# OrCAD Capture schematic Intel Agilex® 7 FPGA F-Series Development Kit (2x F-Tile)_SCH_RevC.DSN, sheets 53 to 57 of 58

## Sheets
53 PG57 VCCIO_SDM, VCCFUSEWR_SDM: size C
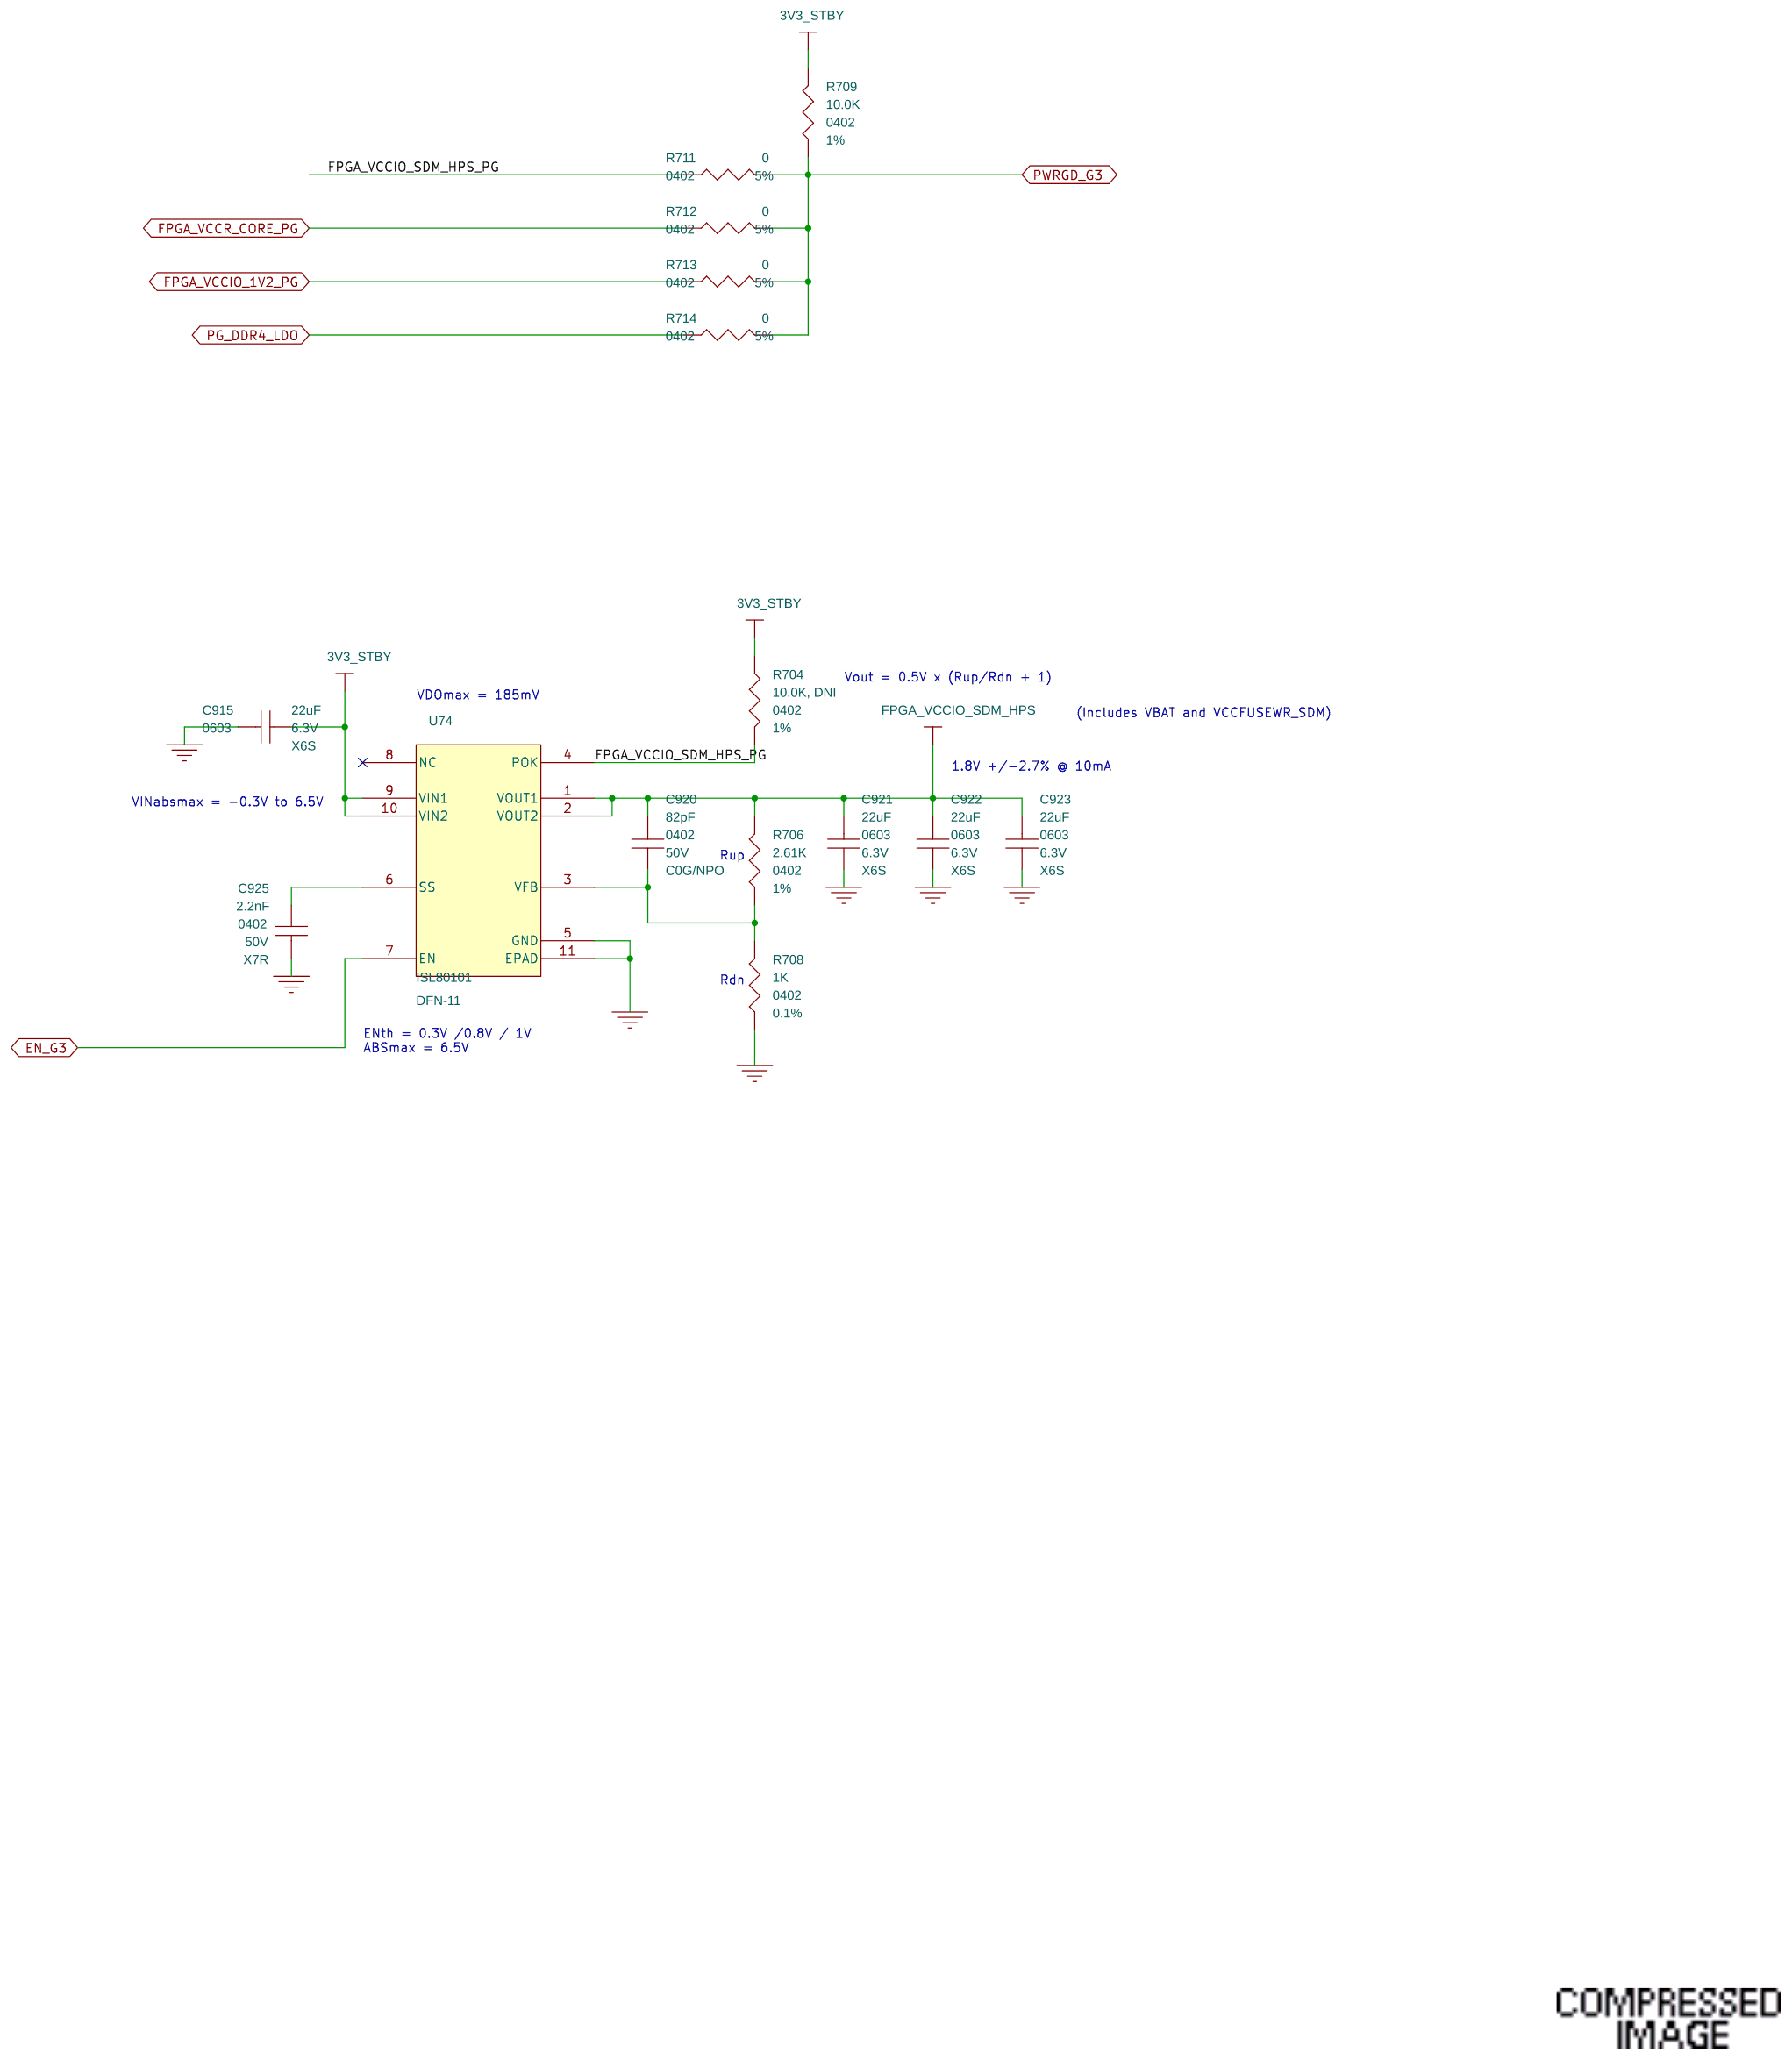
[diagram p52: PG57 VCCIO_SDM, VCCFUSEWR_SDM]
54 PG58 2V5_DDR4, DDR4 VTT, VREF: size C
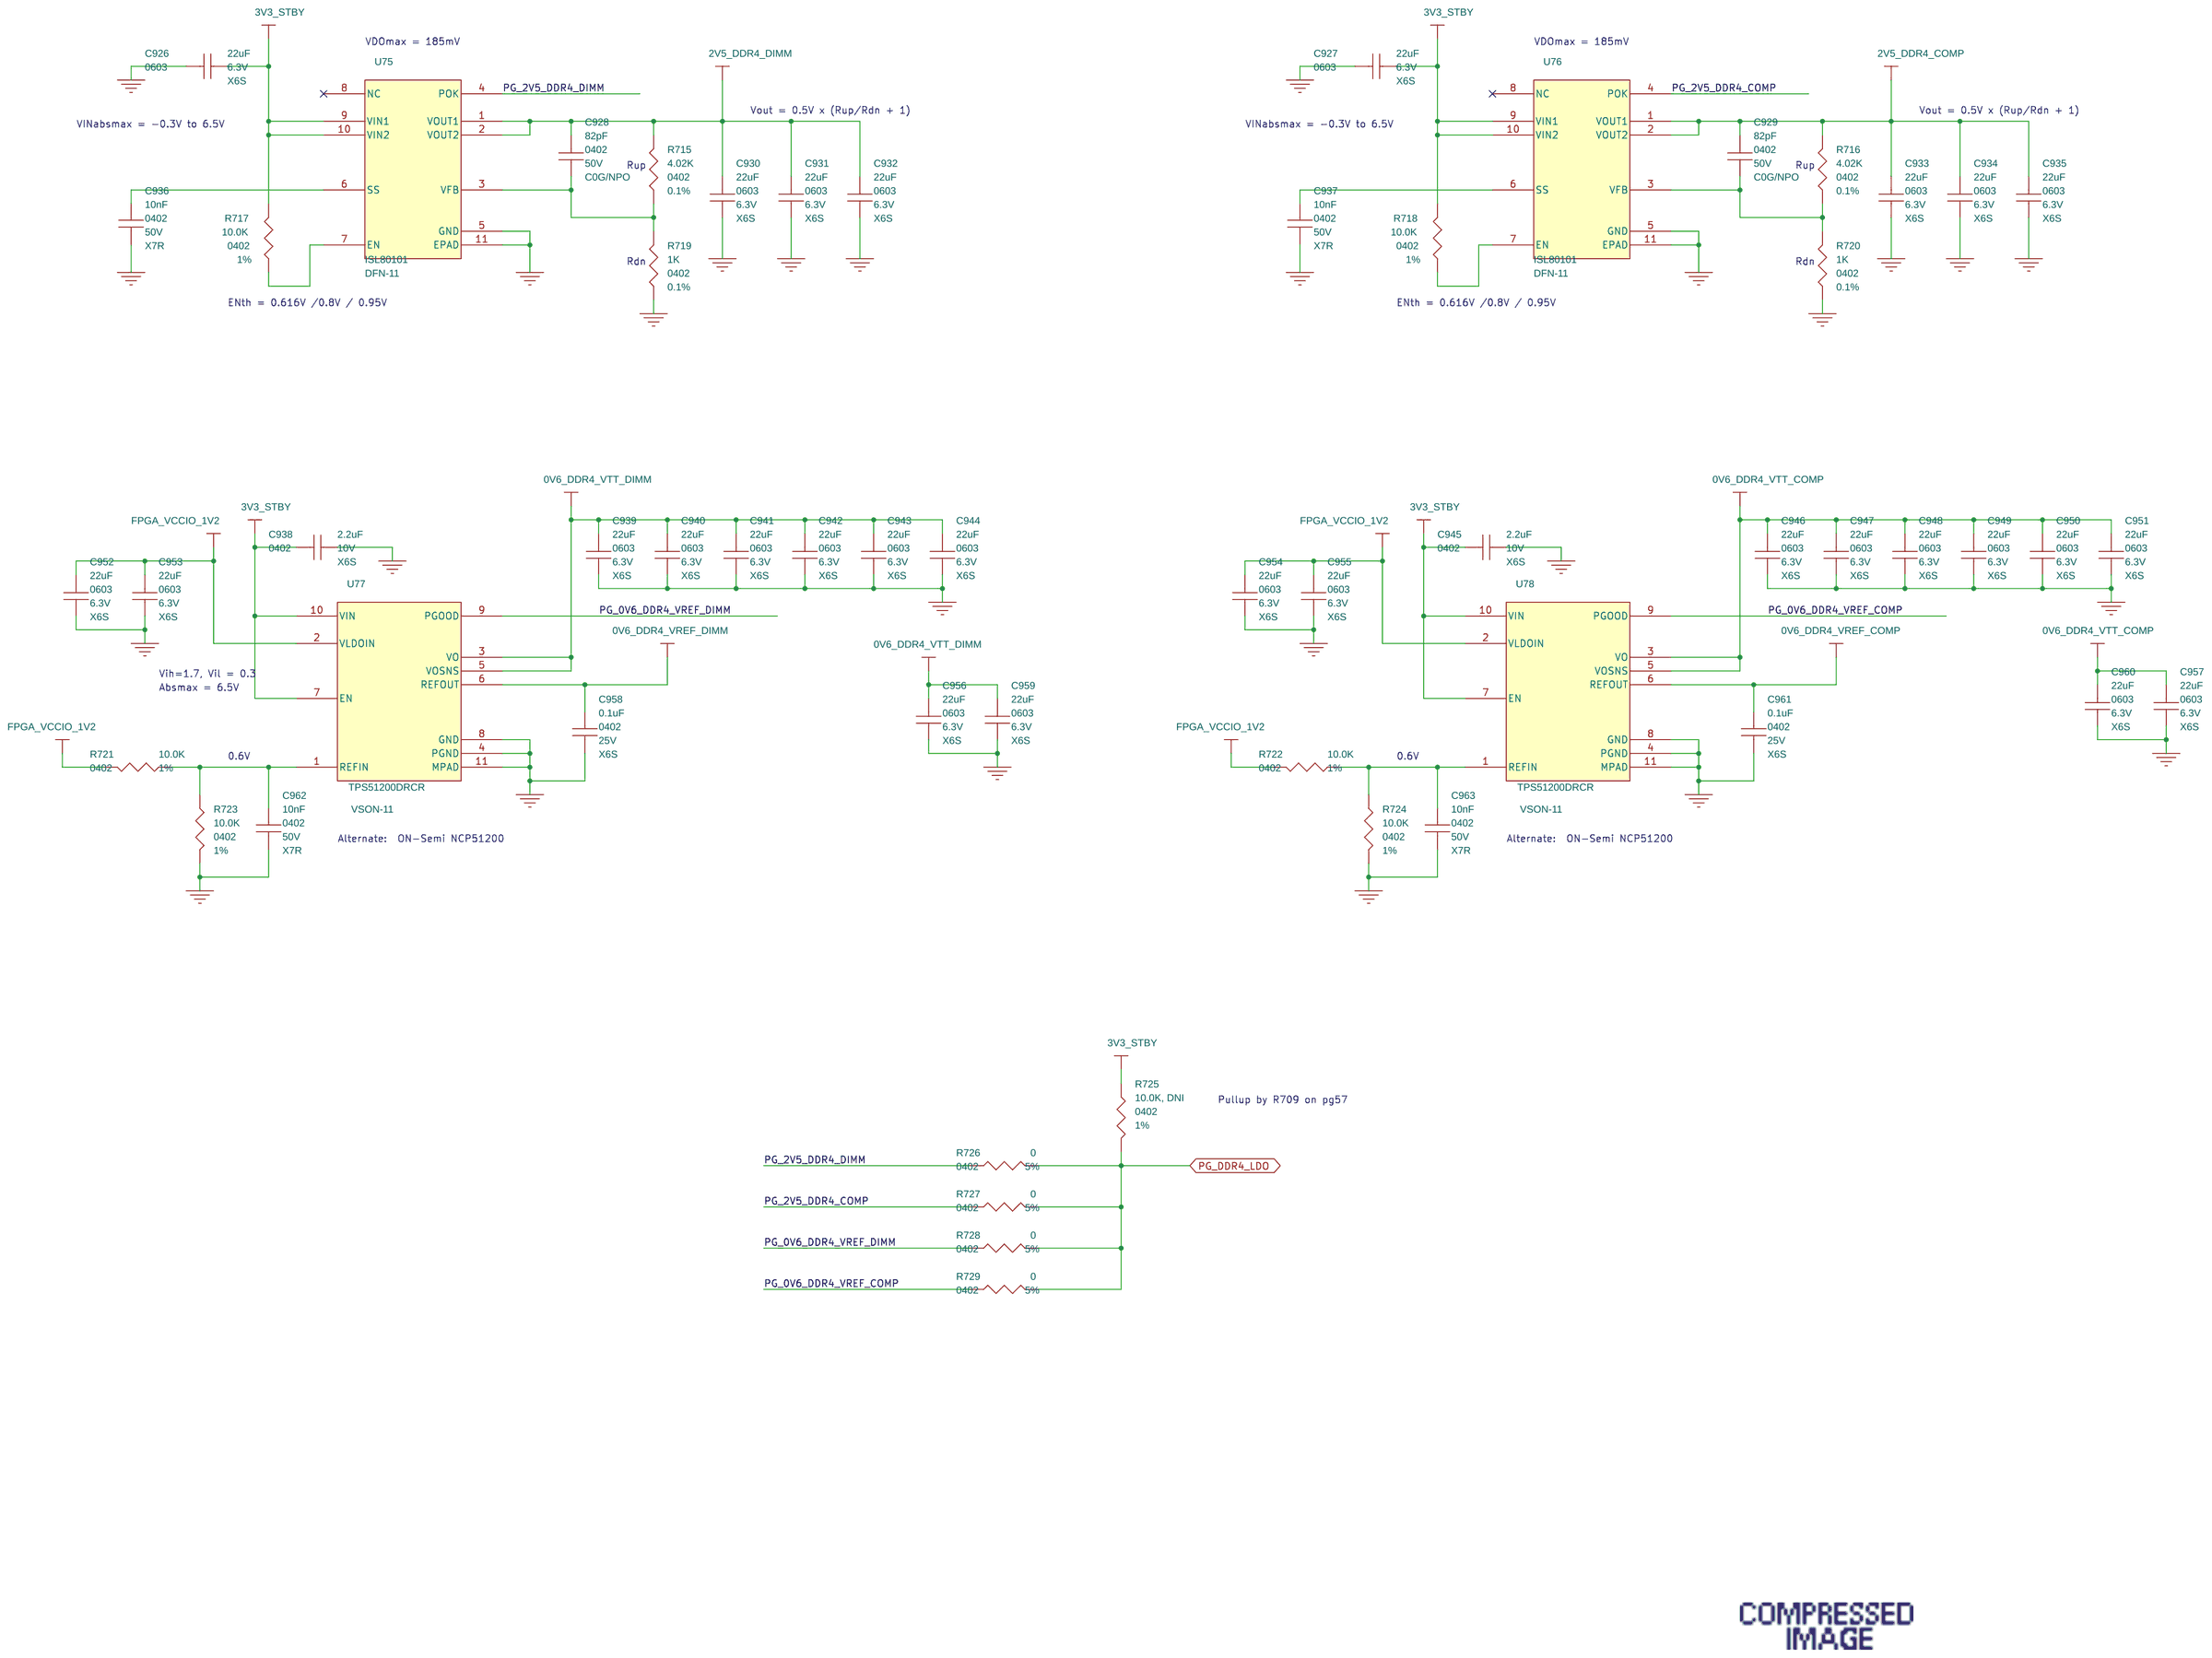
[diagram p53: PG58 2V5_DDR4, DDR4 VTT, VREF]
55 PG26 DDR4/DDR-T DIMM1: size C
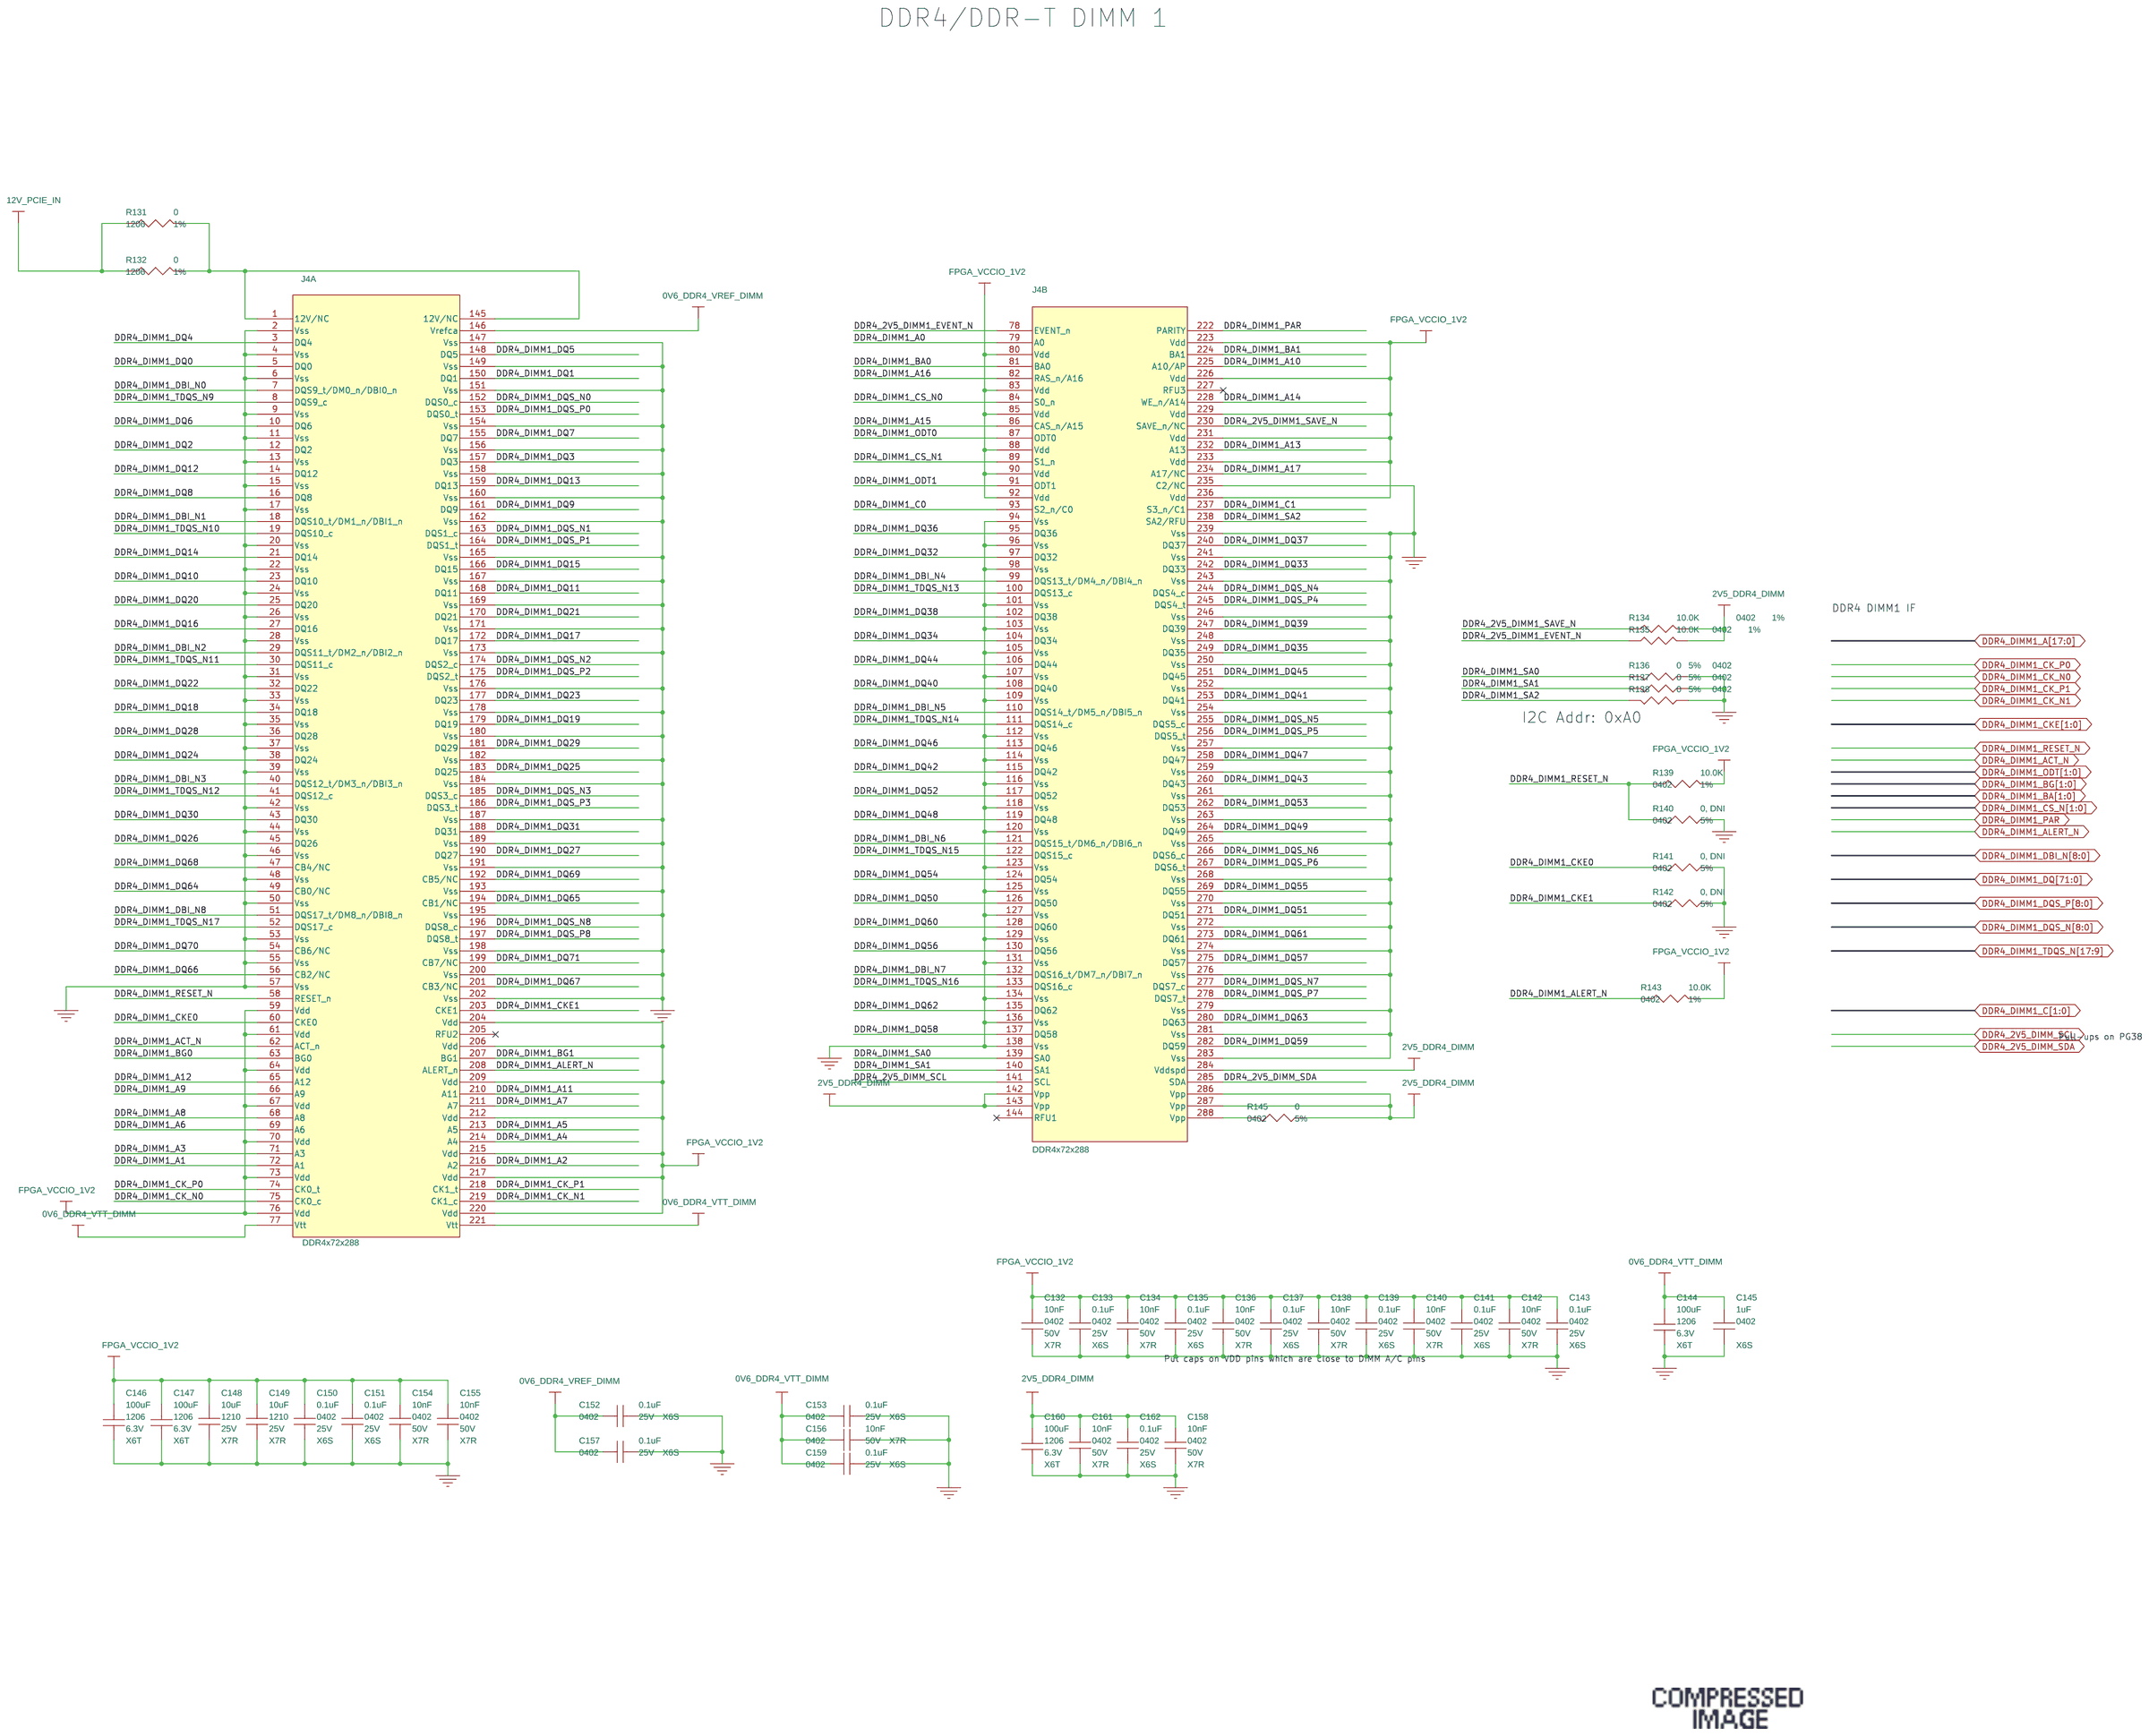
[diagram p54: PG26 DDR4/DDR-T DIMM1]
56 PG27 DDR4/DDR-T DIMM2: size C
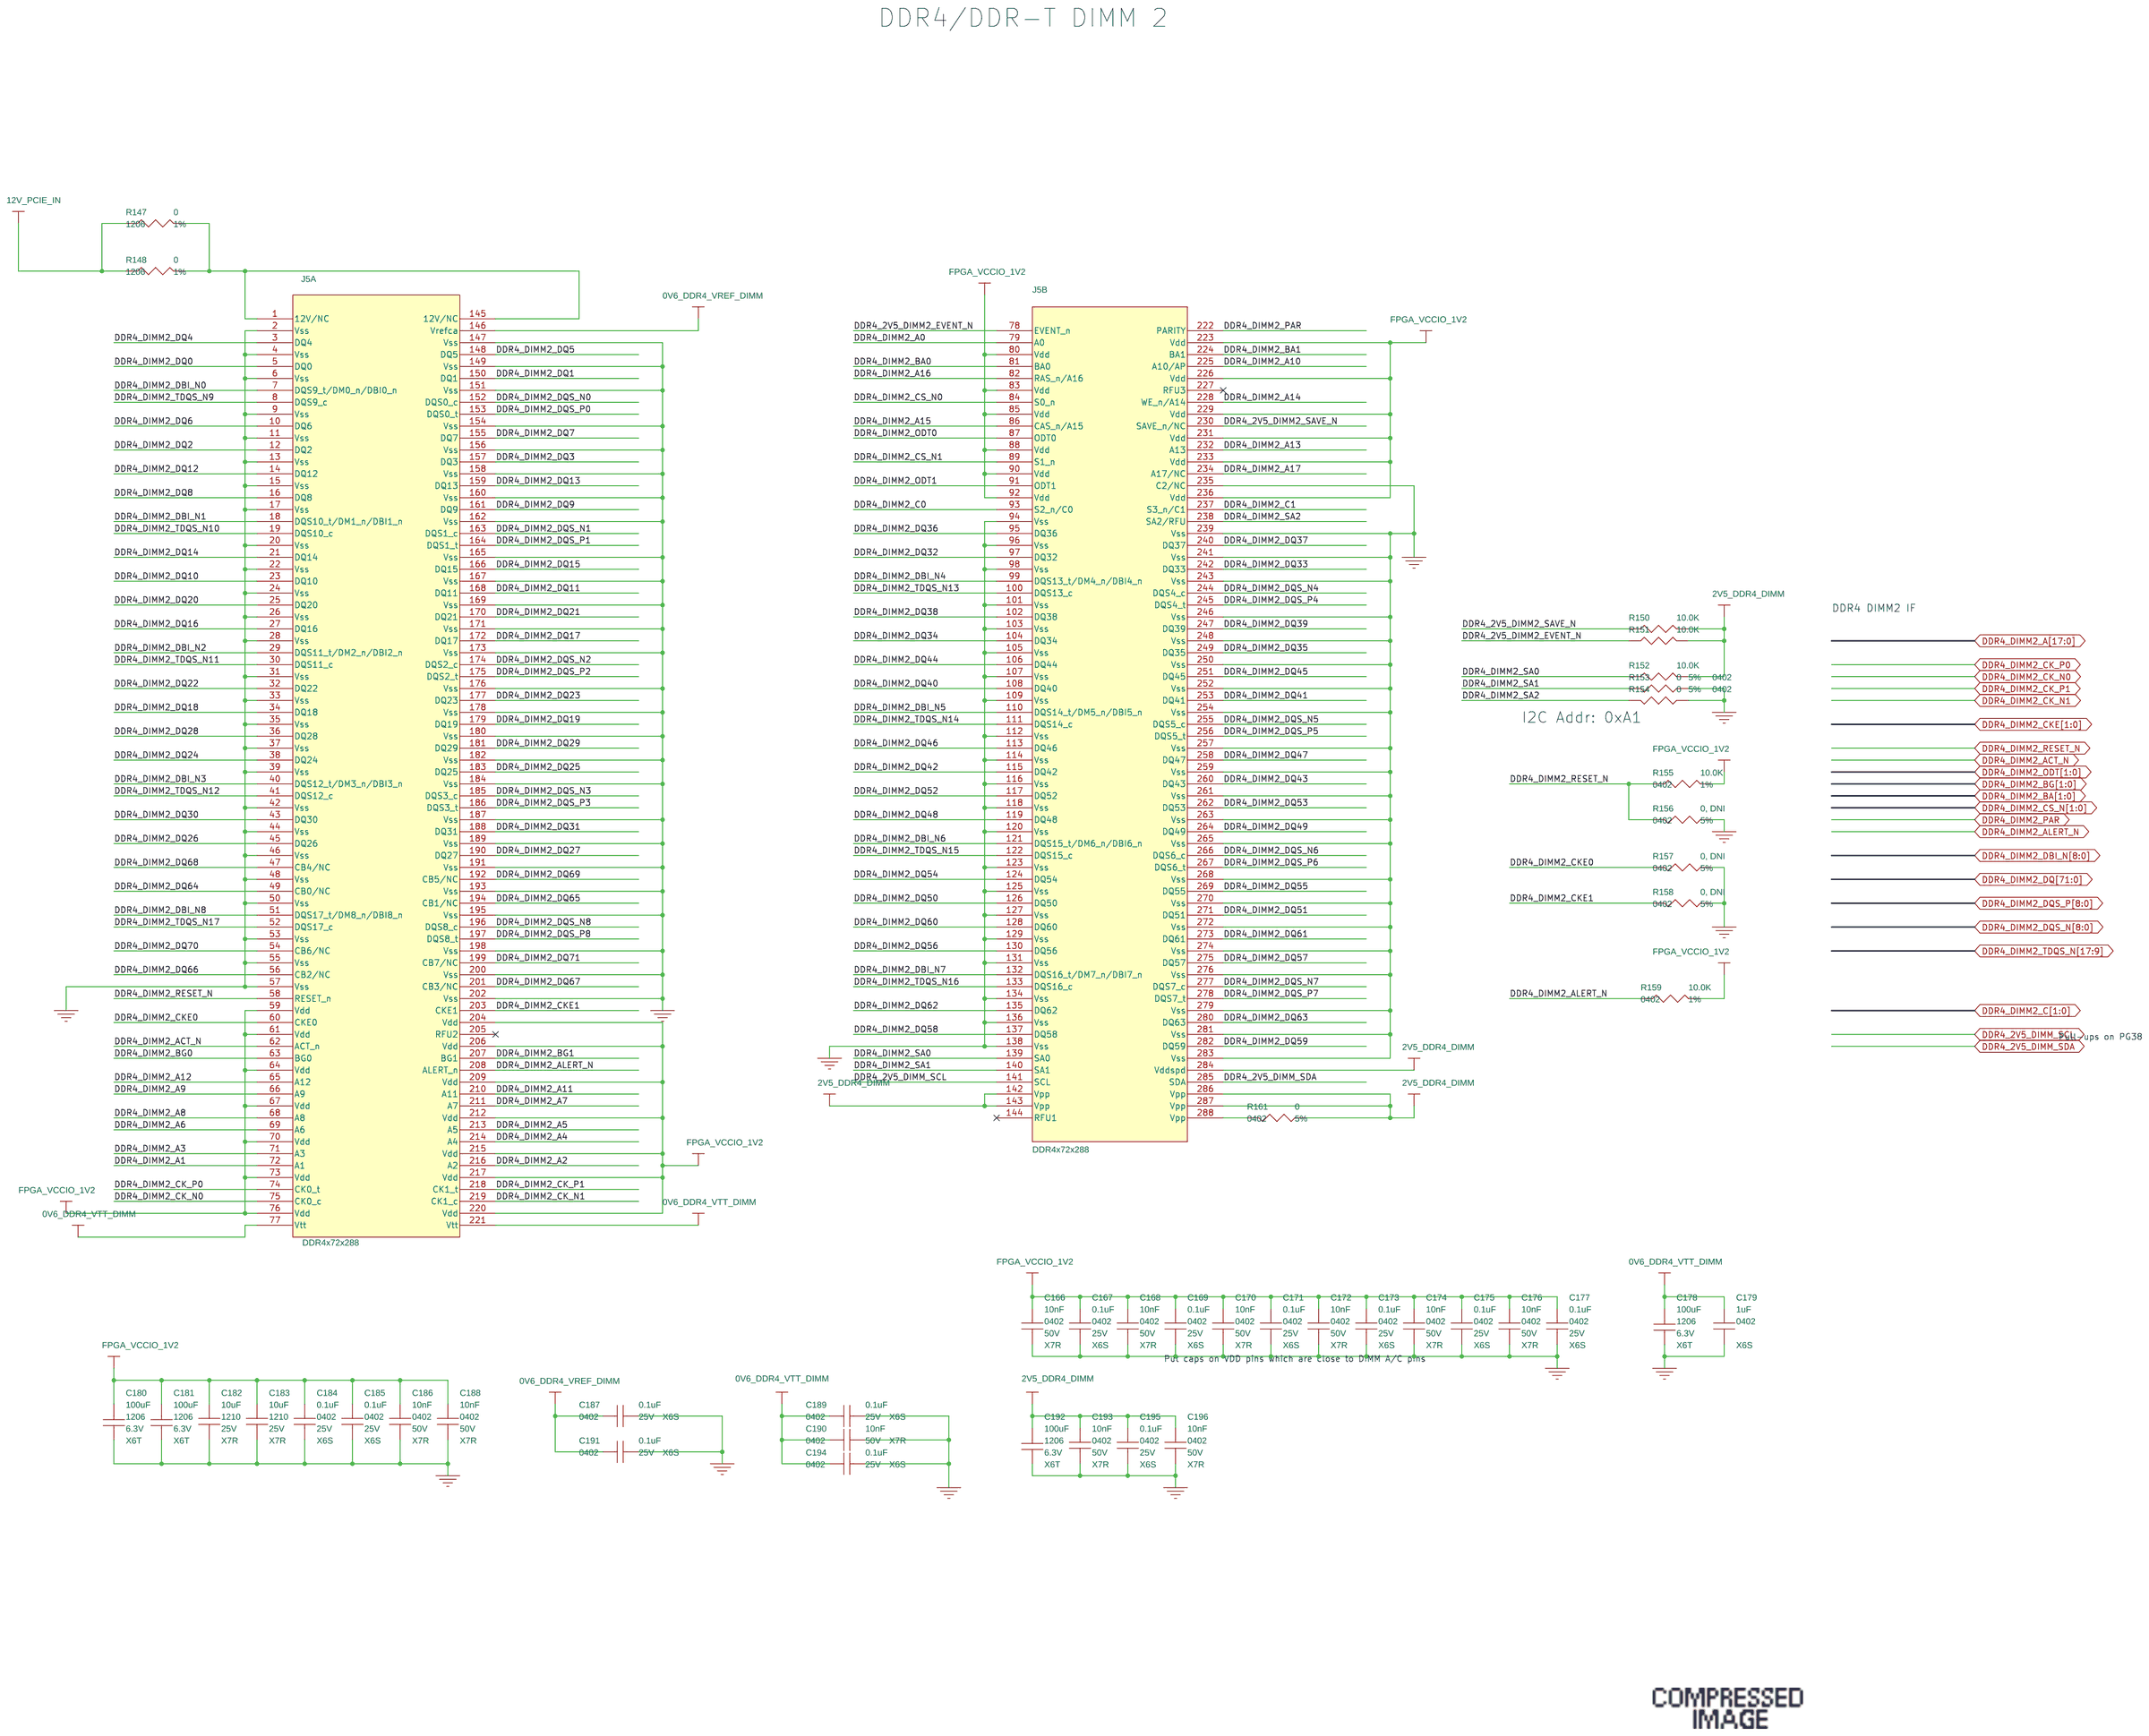
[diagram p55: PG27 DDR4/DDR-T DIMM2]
57 PG25 DDR4/DDR-T PIN MAP
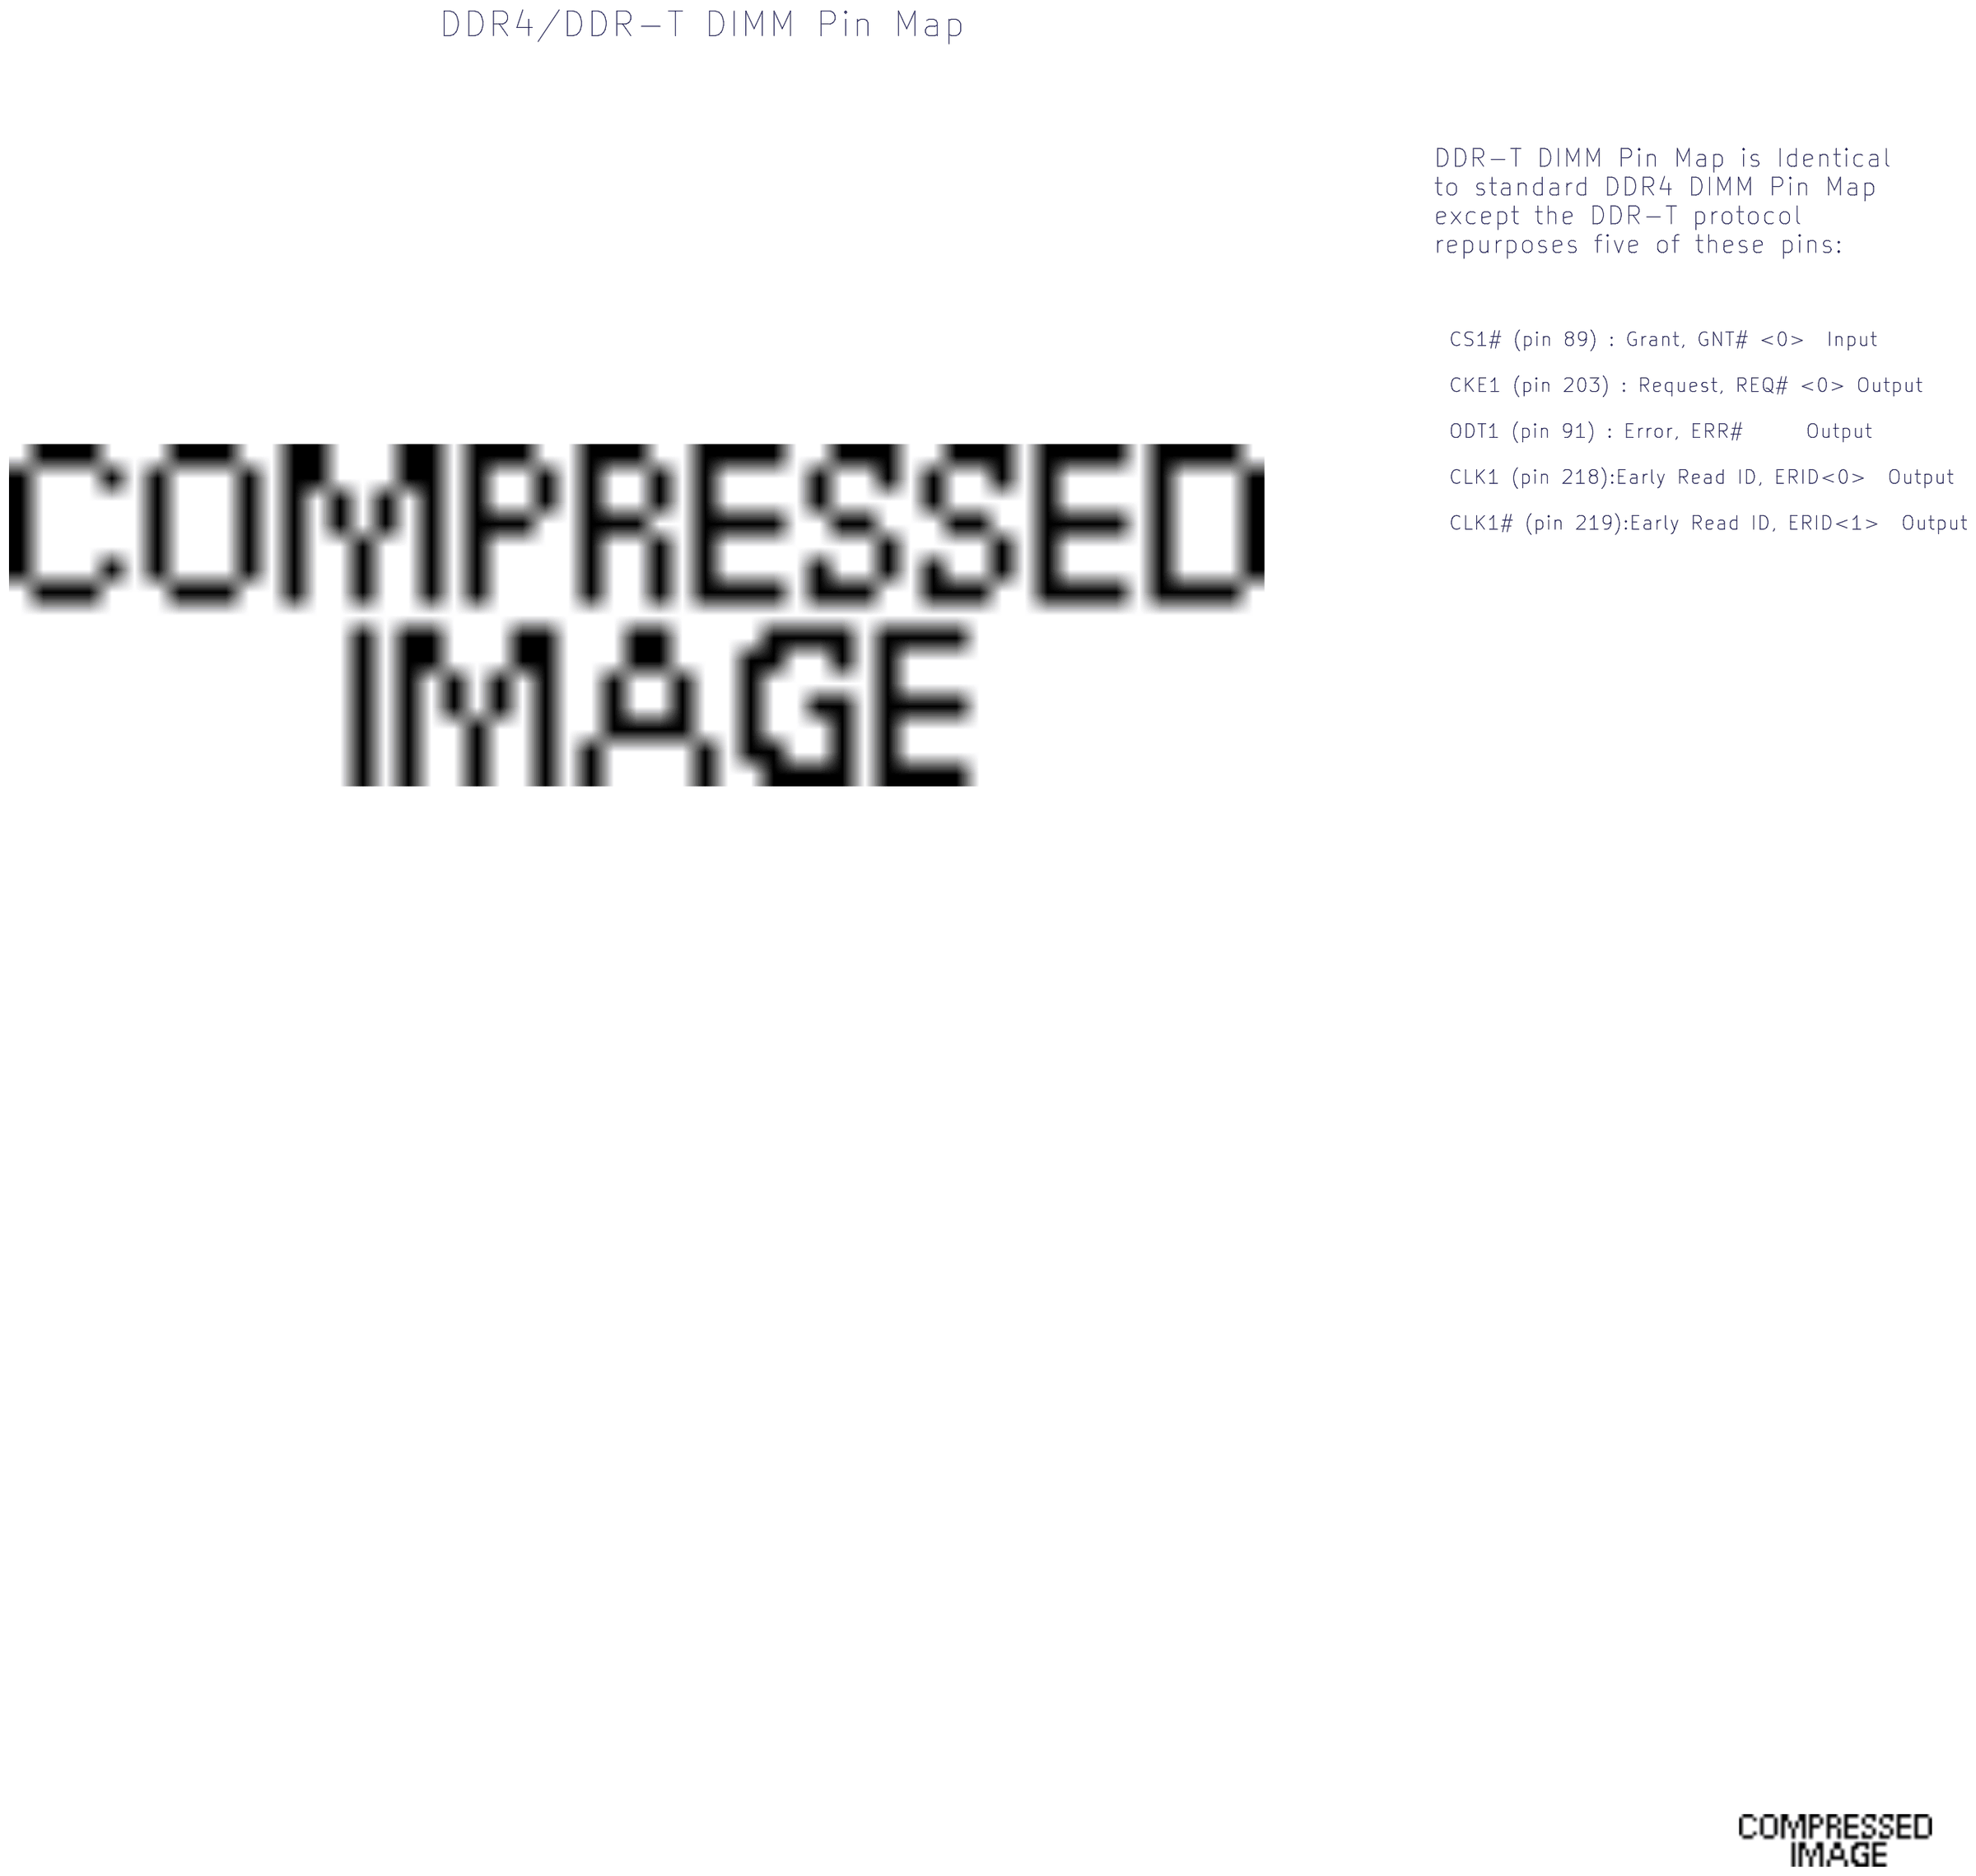
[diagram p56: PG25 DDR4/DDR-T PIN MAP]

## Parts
sheet PG26 DDR4/DDR-T DIMM1
C132  10nF  [0402]
C133  0.1uF  [0402]
C134  10nF  [0402]
C135  0.1uF  [0402]
C136  10nF  [0402]
C137  0.1uF  [0402]
C138  10nF  [0402]
C139  0.1uF  [0402]
C140  10nF  [0402]
C141  0.1uF  [0402]
C142  10nF  [0402]
C143  0.1uF  [0402]
C144  100uF  [1206]
C145  1uF  [0402]
C146  100uF  [1206]
C147  100uF  [1206]
C148  10uF  [1210_H2p2mm]
C149  10uF  [1210_H2p2mm]
C150  0.1uF  [0402]
C151  0.1uF  [0402]
C152  0.1uF  [0402]
C153  0.1uF  [0402]
C154  10nF  [0402]
C155  10nF  [0402]
C156  10nF  [0402]
C157  0.1uF  [0402]
C158  10nF  [0402]
C159  0.1uF  [0402]
C160  100uF  [1206]
C161  10nF  [0402]
C162  0.1uF  [0402]
J4  DDR4x72x288  [DDR4DIMM_SMT]  (sections A,B)
R131  0  [1206]
R132  0  [1206]
R134  10.0K  [0402]
R135  10.0K  [0402]
R136  0  [0402]
R137  0  [0402]
R138  0  [0402]
R139  10.0K  [0402]
R140  0, DNI  [0402]
R141  0, DNI  [0402]
R142  0, DNI  [0402]
R143  10.0K  [0402]
R145  0  [0402]
sheet PG27 DDR4/DDR-T DIMM2
C166  10nF  [0402]
C167  0.1uF  [0402]
C168  10nF  [0402]
C169  0.1uF  [0402]
C170  10nF  [0402]
C171  0.1uF  [0402]
C172  10nF  [0402]
C173  0.1uF  [0402]
C174  10nF  [0402]
C175  0.1uF  [0402]
C176  10nF  [0402]
C177  0.1uF  [0402]
C178  100uF  [1206]
C179  1uF  [0402]
C180  100uF  [1206]
C181  100uF  [1206]
C182  10uF  [1210_H2p2mm]
C183  10uF  [1210_H2p2mm]
C184  0.1uF  [0402]
C185  0.1uF  [0402]
C186  10nF  [0402]
C187  0.1uF  [0402]
C188  10nF  [0402]
C189  0.1uF  [0402]
C190  10nF  [0402]
C191  0.1uF  [0402]
C192  100uF  [1206]
C193  10nF  [0402]
C194  0.1uF  [0402]
C195  0.1uF  [0402]
C196  10nF  [0402]
J5  DDR4x72x288  [DDR4DIMM_SMT]  (sections A,B)
R147  0  [1206]
R148  0  [1206]
R150  10.0K  [0402]
R151  10.0K  [0402]
R152  10.0K  [0402]
R153  0  [0402]
R154  0  [0402]
R155  10.0K  [0402]
R156  0, DNI  [0402]
R157  0, DNI  [0402]
R158  0, DNI  [0402]
R159  10.0K  [0402]
R161  0  [0402]
sheet PG57 VCCIO_SDM, VCCFUSEWR_SDM
C915  22uF  [0603]
C920  82pF  [0402]
C921  22uF  [0603]
C922  22uF  [0603]
C923  22uF  [0603]
C925  2.2nF  [0402]
R704  10.0K, DNI  [0402]
R706  2.61K  [0402]
R708  1K  [0402]
R709  10.0K  [0402]
R711  0  [0402]
R712  0  [0402]
R713  0  [0402]
R714  0  [0402]
U74  ISL80101  [DFN-11]
sheet PG58 2V5_DDR4, DDR4 VTT, VREF
C926  22uF  [0603]
C927  22uF  [0603]
C928  82pF  [0402]
C929  82pF  [0402]
C930  22uF  [0603]
C931  22uF  [0603]
C932  22uF  [0603]
C933  22uF  [0603]
C934  22uF  [0603]
C935  22uF  [0603]
C936  10nF  [0402]
C937  10nF  [0402]
C938  2.2uF  [0402]
C939  22uF  [0603]
C940  22uF  [0603]
C941  22uF  [0603]
C942  22uF  [0603]
C943  22uF  [0603]
C944  22uF  [0603]
C945  2.2uF  [0402]
C946  22uF  [0603]
C947  22uF  [0603]
C948  22uF  [0603]
C949  22uF  [0603]
C950  22uF  [0603]
C951  22uF  [0603]
C952  22uF  [0603]
C953  22uF  [0603]
C954  22uF  [0603]
C955  22uF  [0603]
C956  22uF  [0603]
C957  22uF  [0603]
C958  0.1uF  [0402]
C959  22uF  [0603]
C960  22uF  [0603]
C961  0.1uF  [0402]
C962  10nF  [0402]
C963  10nF  [0402]
R715  4.02K  [0402]
R716  4.02K  [0402]
R717  10.0K  [0402]
R718  10.0K  [0402]
R719  1K  [0402]
R720  1K  [0402]
R721  10.0K  [0402]
R722  10.0K  [0402]
R723  10.0K  [0402]
R724  10.0K  [0402]
R725  10.0K, DNI  [0402]
R726  0  [0402]
R727  0  [0402]
R728  0  [0402]
R729  0  [0402]
U75  ISL80101  [DFN-11]
U76  ISL80101  [DFN-11]
U77  TPS51200DRCR  [VSON-11]
U78  TPS51200DRCR  [VSON-11]

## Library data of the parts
C132 C134 C136 C138 C140 C142 C154-C156 C158 C161 C166 C168 C170 C172 C174 C176 C186 C188 C190 C193 C196 = Cap_10000PF_50V_0402: CAP - CER, 10NF, 50V, +/-10%, X7R, 0402 SMD; Dielectric: X7R; Item Num: H61346-001; LIFECYCLE_PHASE: Active; Lead Free Status: Lead Free; Manufacturer Part Num: GRM155R71H103KA88D; Num Pins: 2; Part Class: CAPACITORS; RATED_VOLTAGE: 50V; RoHS Compliant: RoHS Compliant; Temperature Coefficient: X7R; Tolerance: 10%; Voltage: 50V
C133 C135 C137 C139 C141 C143 C150-C153 C157 C159 C162 C167 C169 C171 C173 C175 C177 C184 C185 C187 C189 C191 C194 C195 C958 C961 = CAP: CAP CER 0.1UF 25V X6S 0402; Dielectric: X6S; IPN: K19434-001; Item Num: K19434-001; LIFECYCLE_PHASE: Active; Lead Free Status: Lead Free; MFR_LIFECYCLE: Active; Manufacturer: Murata; Manufacturer Part Num: GRM155C81E104KA12D; Num Pins: 2; PART_SUBCLASS: CAPACITORS; Part Class: CAPACITORS; RATED_VOLTAGE: 25V; RoHS Compliant: RoHS Compliant; Temperature Coefficient: X6S; Tolerance: 10%
C144 C146 C147 C160 C178 C180 C181 = CAP: CAP CER 100UF 6.3V X6T 1206; CLASS: DISCRETE; Dielectric Type: X6T; Item Num: H65271-004; LIFECYCLE_PHASE: Active; Lead Free Status: Lead Free; MFR_LIFECYCLE: Active; Manufacturer: Murata; Manufacturer PN: GRM31CR60J107ME39L; Manufacturer Part Num: GRM31CD80J107ME39L; Num Pins: 2; PART_SUBCLASS: CAPACITORS; RATED_VOLTAGE: 6.3V; Rated Voltage: 6.3V; RoHS Compliant: RoHS Compliant; TOLERANCE: 20%; Temperature Coefficient: X6T; Working Voltage: 6.3V
C145 C179 = CAP: CAP CER 1UF 25V X6S 0402; Item Num: H81594-001; Lead Free Status: Yes; Manufacturer: Murata; Manufacturer Part Num: GRM155C81E105KE11D; Num Pins: 2; Part Class: CAPACITORS; RATED_VOLTAGE: 25V; RoHS Compliant: Yes; Temperature Coefficient: X6S
C148 C149 C182 C183 = CAP_10uF_+_-10%_25V_1210: CAP - CER, 10UF, 25V, 10%, X7R, 1210; Agile Part Description: CAP - CER, 10UF, 25V, 10%, X7R, 1210; Item Num: G10603-003; Manufacturer Part Num: GRM32DR71E106KA12L; Package: 1210; Temperature Coefficient: X7R; Voltage: 25V
J4 = DDR4x72x288_1: CONN SMT DDR4 288POS VERT; COMPGROUP: DDR4_DIMM1; Item Num: K21528-001; Manufacturer: Molex Inc; Manufacturer Part Num: 787301002
R131 R132 R147 R148 = RESISTOR: RES SMD 0 OHM JUMPER 3/4W 1206; AGILE_LINK: http://sj-agile9app/Agile/PLMServlet?action=OpenEmailObject&classid=10000&objid=146548997; Item Num: A93552-015; LIFECYCLE_PHASE: Active; Lead Free Status: No; MFR_LIFECYCLE: Active; Manufacturer: Vishay Dale; Manufacturer Part Num: CRCW12060000Z0EAHP; Num Pins: 2; PART_SUBCLASS: RESISTORS; POWER: 3/4W; RoHS Compliant: Yes; TOLERANCE: 1%
R134 R135 R139 R143 R150-R152 R155 R159 R709 R717 R718 R721-R724 = RESISTOR: RES,10.0K OHMS,1.0%,1/16W, 0402; AGILE_LINK: http://sj-agile9app/Agile/PLMServlet?action=OpenEmailObject&classid=10000&objid=146548997; Item Num: K28115-001; LIFECYCLE_PHASE: Active; Lead Free Status: Yes; MFR_LIFECYCLE: Active; Manufacturer: Panasonic; Manufacturer Part Num: ERJ-2RKF1002X; Num Pins: 2; PART_SUBCLASS: RESISTORS; POWER: 1/16W; RoHS Compliant: Yes; TOLERANCE: 1%
R136-R138 R145 R153 R154 R161 = RES_0_OHM_5%_1_16W_0402_SMD: Item Num: A93549-001; Manufacturer: Yageo; Manufacturer Part Num: RC0402JR-070RL; Num Pins: 2; RoHS Compliant: Yes; Tolerance: 5%
R140-R142 R156-R158 = RES_0_OHM_5%_1_16W_0402_SMD: IPN: A93549-001; Item Num: A93549-001; Lead Free Status: Yes; Manufacturer: Yageo; Manufacturer Part Num: RC0402JR-070RL; Num Pins: 2; Part Class: RESISTORS; RoHS Compliant: Yes; Tolerance: 5%
C192 = CAP: CAP CER 100UF 6.3V X6T 1206; Dielectric Type: X6T; Item Num: H65271-004; LIFECYCLE_PHASE: Active; Lead Free Status: Lead Free; MFR_LIFECYCLE: Active; Manufacturer: Murata; Manufacturer PN: GRM31CD80J107ME39L; Manufacturer Part Num: GRM31CD80J107ME39L; Num Pins: 2; PART_SUBCLASS: CAPACITORS; RATED_VOLTAGE: 6.3V; Rated Voltage: 6.3V; RoHS Compliant: RoHS Compliant; TOLERANCE: 20%; Temperature Coefficient: X6T; Working Voltage: 6.3V
J5 = DDR4x72x288_1: CONN SMT DDR4 288POS VERT; COMPGROUP: DDR4_DIMM2; Item Num: K21528-001; Manufacturer: Molex Inc; Manufacturer Part Num: 787301002
C915 C921-C923 C926 C927 C930-C935 C939-C944 C946-C957 C959 C960 = CAP: CAP CER 22UF 6.3V X6S 0603; AGILE_LINK: http://sj-agile9app/Agile/PLMServlet?action=OpenEmailObject&classid=10000&objid=257560276; Item Num: H63299-001; LIFECYCLE_PHASE: Active; Lead Free Status: Not Lead Free; MFR_LIFECYCLE: Active; Manufacturer: Murata; Manufacturer Part Num: GRM188C80J226ME15D; Num Pins: 2; PART_SUBCLASS: CAPACITORS; RATED_VOLTAGE: 6.3V; RoHS Compliant: RoHS Compliant; TOLERANCE: 20%; Temperature Coefficient: X6S
C920 C928 C929 = CAP: CAP CER 82PF 50V C0G/NPO 0402; Dielectric: C0G/NPO; Item Num: K13615-001; Lead Free Status: Yes; Manufacturer: Yageo; Manufacturer Part Num: CC0402JRNPO9BN820; Num Pins: 2; Part Class: CAPACITORS; RoHS Compliant: Yes; Temperature Coefficient: C0G/NPO; Tolerance: 5%; Voltage Rating: 50V
C925 = CAP: CAP CER 2200PF 50V 10% X7R 0402; CAPACITANCE: 2200pF; Dielectric: X7R; Item Num: K13631-001; LIFECYCLE_PHASE: Active; Lead Free Status: Lead Free; Manufacturer: TDK; Manufacturer Part Num: CGJ2B2X7R1E222K050BA; Num Pins: 2; PART_SUBCLASS: CAPACITORS; Part Class: CAPACITORS; RATED_VOLTAGE: 50V; RoHS Compliant: RoHS Compliant; Temperature Coefficient: X7R; Tolerance: +/-10%
R704 R725 = RESISTOR: RES,10.0K OHMS,1.0%,1/16W, 0402; AGILE_LINK: http://sj-agile9app/Agile/PLMServlet?action=OpenEmailObject&classid=10000&objid=146548997; Item Num: K28115-001; LIFECYCLE_PHASE: Active; Lead Free Status: Yes; MFR_LIFECYCLE: Active; Manufacturer: Panasonic; Manufacturer Part Num: ERJ-2RKF1002X; Num Pins: 2; PART_SUBCLASS: RESISTORS; POWER: 1/16W; RESISTANCE: 10.0K; RoHS Compliant: Yes; TOLERANCE: 1%
R706 = RESISTOR: RES SMD 2.61K 1% 1/16W 0402; Item Num: A93548-419; Lead Free Status: Yes; Manufacturer: RC0402FR-072K61L; Manufaturer: Yageo; Num Pins: 2; Part Class: RESISTORS; RoHS Compliant: Yes; TOLERANCE: 1%
R708 R719 R720 = RESISTOR: RES SMD 1K OHM 0.1% 1/16W 0402; Item Num: K21643-001; Lead Free Status: Yes; Manufacturer: Panasonic; Manufacturer Part Num: ERA-2AEB102X; Num Pins: 2; Part Class: Resistors; Power Rating: 1/16W; RoHS Compliant: Yes; TOLERANCE: 0.1%
R711-R714 R726-R729 = RESISTOR: RES ZERO OHM 1/16W 5% 0402 SMD; Item Num: A93549-001; Lead Free Status: Yes; Manufacturer: Yageo; Manufacturer Part Num: RC0402JR-070RL; Num Pins: 2; Part Class: RESISTORS; RoHS Compliant: Yes; Tolerance: 5%
U74-U76 = EY1501di-adj: IC, Linear Regulator, 1A; Item Num: E81353-001; Manufacturer: Intel/Enpirion; Manufacturer Part Num: EY1501DI-ADJ
C936 C937 C962 C963 = CAP: CAP - CER, 10NF, 50V, +/-10%, X7R, 0402 SMD; Dielectric: X7R; Item Num: H61346-001; LIFECYCLE_PHASE: Active; Lead Free Status: Lead Free; Manufacturer: Murata; Manufacturer Part Num: GRM155R71H103KA88D; Num Pins: 2; Part Class: CAPACITORS; RATED_VOLTAGE: 50V; RoHS Compliant: RoHS Compliant; Temperature Coefficient: X7R; Tolerance: 10%; Voltage: 50V
C938 C945 = CAP: CAP CER 2.2UF 10V X6S 0402; Dielectric: X6S; Item Num: H90637-001; LIFECYCLE_PHASE: Active; Lead Free Status: Lead Free; Manufacturer: Murata; Manufacturer Part Num: GRM155C81A225KE44D; Num Pins: 2; Part Class: CAPACITORS; RATED_VOLTAGE: 10V; RoHS Compliant: RoHS Compliant; Tolerance: 10%
R715 R716 = RESISTOR: RES SMD 4.02KOHM 0.1% 1/16W 0402; Item Num: K21642-001; Lead Free Status: Yes; Manufacturer: Panasonic; Manufacturer Part Num: ERA-2AEB4021X; Num Pins: 2; Part Class: RESISTORS; RoHS Compliant: Yes; TOLERANCE: 0.1%
U77 U78 = TPS51200_1: IC, Sink and Source DDR Termination Regulator; Item Num: H28999-001; Manufacturer: Texas Instruments

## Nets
0V6_DDR4_VREF_COMP: C961.1 U78.6(REFOUT) ; also on sheet 25 26 27
0V6_DDR4_VREF_DIMM: C152.1 C157.1 C187.1 C191.1 C958.1 J4.146(Vrefca) J5.146(Vrefca) U77.6(REFOUT)
0V6_DDR4_VTT_COMP: C946.2 C947.2 C948.2 C949.2 C950.2 C951.2 C957.2 C960.2 U78.3(VO) U78.5(VOSNS) ; also on sheet 23 27
0V6_DDR4_VTT_DIMM: C144.2 C145.1 C153.1 C156.1 C159.1 C178.2 C179.1 C189.1 C190.1 C194.1 C939.2 C940.2 C941.2 C942.2 C943.2 C944.2 C956.2 C959.2 J4.77(Vtt) J4.221(Vtt) J5.77(Vtt) J5.221(Vtt) U77.3(VO) U77.5(VOSNS) ; also on sheet 23
2V5_DDR4_COMP: C929.2 C933.2 C934.2 C935.2 R716.2 U76.1(VOUT1) U76.2(VOUT2) ; also on sheet 25 26 27
2V5_DDR4_DIMM: C158.1 C160.2 C161.1 C162.1 C192.2 C193.1 C195.1 C196.1 C928.2 C930.2 C931.2 C932.2 J4.142(Vpp) J4.143(Vpp) J4.284(Vddspd) J4.286(Vpp) J4.287(Vpp) J5.142(Vpp) J5.143(Vpp) J5.284(Vddspd) J5.286(Vpp) J5.287(Vpp) R134.2 R135.2 R145.1 R150.2 R151.2 R152.2 R161.1 R715.2 U75.1(VOUT1) U75.2(VOUT2) ; also on sheet 35
3V3_STBY: C915.1 C926.1 C927.1 C938.2 C945.2 R704.1 R709.2 R717.1 R718.1 R725.1 U74.9(VIN1) U74.10(VIN2) U75.9(VIN1) U75.10(VIN2) U76.9(VIN1) U76.10(VIN2) U77.7(EN) U77.10(VIN) U78.7(EN) U78.10(VIN) ; also on sheet 8 10 16 22 28 32 34 36 37 38 40 41 48 49 50 51 52 58
12V_PCIE_IN: R131.1 R132.1 R147.1 R148.1 ; also on sheet 28 40 41 47 49 50
GND: C132.2 C133.2 C134.2 C135.2 C136.2 C137.2 C138.2 C139.2 C140.2 C141.2 C142.2 C143.2 C144.1 C145.2 C146.1 C147.1 C148.2 C149.2 C150.2 C151.2 C152.2 C153.2 C154.2 C155.2 C156.2 C157.2 C158.2 C159.2 C160.1 C161.2 C162.2 C166.2 C167.2 C168.2 C169.2 C170.2 C171.2 C172.2 C173.2 C174.2 C175.2 C176.2 C177.2 C178.1 C179.2 C180.1 C181.1 C182.2 C183.2 C184.2 C185.2 C186.2 C187.2 C188.2 C189.2 C190.2 C191.2 C192.1 C193.2 C194.2 C195.2 C196.2 C915.2 C921.1 C922.1 C923.1 C925.2 C926.2 C927.2 C930.1 C931.1 C932.1 C933.1 C934.1 C935.1 C936.2 C937.2 C938.1 C939.1 C940.1 C941.1 C942.1 C943.1 C944.1 C945.1 C946.1 C947.1 C948.1 C949.1 C950.1 C951.1 C952.1 C953.1 C954.1 C955.1 C956.1 C957.1 C958.2 C959.1 C960.1 C961.2 C962.2 C963.2 J4.2(Vss) J4.4(Vss) J4.6(Vss) J4.9(Vss) J4.11(Vss) J4.13(Vss) J4.15(Vss) J4.17(Vss) J4.20(Vss) J4.22(Vss) J4.24(Vss) J4.26(Vss) J4.28(Vss) J4.31(Vss) J4.33(Vss) J4.35(Vss) J4.37(Vss) J4.39(Vss) J4.42(Vss) J4.44(Vss) J4.46(Vss) J4.48(Vss) J4.50(Vss) J4.53(Vss) J4.55(Vss) J4.57(Vss) J4.94(Vss) J4.96(Vss) J4.98(Vss) J4.101(Vss) J4.103(Vss) J4.105(Vss) J4.107(Vss) J4.109(Vss) J4.112(Vss) J4.114(Vss) J4.116(Vss) J4.118(Vss) J4.120(Vss) J4.123(Vss) J4.125(Vss) J4.127(Vss) J4.129(Vss) J4.131(Vss) J4.134(Vss) J4.136(Vss) J4.138(Vss) J4.147(Vss) J4.149(Vss) J4.151(Vss) J4.154(Vss) J4.156(Vss) J4.158(Vss) J4.160(Vss) J4.162(Vss) J4.165(Vss) J4.167(Vss) J4.169(Vss) J4.171(Vss) J4.173(Vss) J4.176(Vss) J4.178(Vss) J4.180(Vss) J4.182(Vss) J4.184(Vss) J4.187(Vss) J4.189(Vss) J4.191(Vss) J4.193(Vss) J4.195(Vss) J4.198(Vss) J4.200(Vss) J4.202(Vss) J4.235(C2/NC) J4.239(Vss) J4.241(Vss) J4.243(Vss) J4.246(Vss) J4.248(Vss) J4.250(Vss) J4.252(Vss) J4.254(Vss) J4.257(Vss) J4.259(Vss) J4.261(Vss) J4.263(Vss) J4.265(Vss) J4.268(Vss) J4.270(Vss) J4.272(Vss) J4.274(Vss) J4.276(Vss) J4.279(Vss) J4.281(Vss) J4.283(Vss) J5.2(Vss) J5.4(Vss) J5.6(Vss) J5.9(Vss) J5.11(Vss) J5.13(Vss) J5.15(Vss) J5.17(Vss) J5.20(Vss) J5.22(Vss) J5.24(Vss) J5.26(Vss) J5.28(Vss) J5.31(Vss) J5.33(Vss) J5.35(Vss) J5.37(Vss) J5.39(Vss) J5.42(Vss) J5.44(Vss) J5.46(Vss) J5.48(Vss) J5.50(Vss) J5.53(Vss) J5.55(Vss) J5.57(Vss) J5.94(Vss) J5.96(Vss) J5.98(Vss) J5.101(Vss) J5.103(Vss) J5.105(Vss) J5.107(Vss) J5.109(Vss) J5.112(Vss) J5.114(Vss) J5.116(Vss) J5.118(Vss) J5.120(Vss) J5.123(Vss) J5.125(Vss) J5.127(Vss) J5.129(Vss) J5.131(Vss) J5.134(Vss) J5.136(Vss) J5.138(Vss) J5.147(Vss) J5.149(Vss) J5.151(Vss) J5.154(Vss) J5.156(Vss) J5.158(Vss) J5.160(Vss) J5.162(Vss) J5.165(Vss) J5.167(Vss) J5.169(Vss) J5.171(Vss) J5.173(Vss) J5.176(Vss) J5.178(Vss) J5.180(Vss) J5.182(Vss) J5.184(Vss) J5.187(Vss) J5.189(Vss) J5.191(Vss) J5.193(Vss) J5.195(Vss) J5.198(Vss) J5.200(Vss) J5.202(Vss) J5.235(C2/NC) J5.239(Vss) J5.241(Vss) J5.243(Vss) J5.246(Vss) J5.248(Vss) J5.250(Vss) J5.252(Vss) J5.254(Vss) J5.257(Vss) J5.259(Vss) J5.261(Vss) J5.263(Vss) J5.265(Vss) J5.268(Vss) J5.270(Vss) J5.272(Vss) J5.274(Vss) J5.276(Vss) J5.279(Vss) J5.281(Vss) J5.283(Vss) R136.1 R137.1 R138.1 R140.1 R141.1 R142.1 R153.1 R154.1 R156.1 R157.1 R158.1 R708.2 R719.2 R720.2 R723.2 R724.2 U74.5(GND) U74.11(EPAD) U75.5(GND) U75.11(EPAD) U76.5(GND) U76.11(EPAD) U77.4(PGND) U77.8(GND) U77.11(MPAD) U78.4(PGND) U78.8(GND) U78.11(MPAD) ; also on sheet 8 9 10 11 12 13 15 16 19 20 21 22 23 24 25 26 27 28 29 30 31 32 33 34 35 36 37 38 39 40 41 42 43 44 45 46 47 48 49 50 51 52 58
DDR4_2V5_DIMM1_EVENT_N: J4.78(EVENT_n) R135.1
DDR4_2V5_DIMM1_SAVE_N: J4.230(SAVE_n/NC) R134.1
DDR4_2V5_DIMM2_EVENT_N: J5.78(EVENT_n) R151.1
DDR4_2V5_DIMM2_SAVE_N: J5.230(SAVE_n/NC) R150.1
DDR4_2V5_DIMM_SCL: J4.141(SCL) J5.141(SCL) ; also on sheet 35
DDR4_2V5_DIMM_SDA: J4.285(SDA) J5.285(SDA) ; also on sheet 35
DDR4_DIMM1_A0: J4.79(A0) ; also on sheet 12
DDR4_DIMM1_A1: J4.72(A1) ; also on sheet 12
DDR4_DIMM1_A2: J4.216(A2) ; also on sheet 12
DDR4_DIMM1_A3: J4.71(A3) ; also on sheet 12
DDR4_DIMM1_A4: J4.214(A4) ; also on sheet 12
DDR4_DIMM1_A5: J4.213(A5) ; also on sheet 12
DDR4_DIMM1_A6: J4.69(A6) ; also on sheet 12
DDR4_DIMM1_A7: J4.211(A7) ; also on sheet 12
DDR4_DIMM1_A8: J4.68(A8) ; also on sheet 12
DDR4_DIMM1_A9: J4.66(A9) ; also on sheet 12
DDR4_DIMM1_A10: J4.225(A10/AP) ; also on sheet 12
DDR4_DIMM1_A11: J4.210(A11) ; also on sheet 12
DDR4_DIMM1_A12: J4.65(A12) ; also on sheet 12
DDR4_DIMM1_A13: J4.232(A13) ; also on sheet 12
DDR4_DIMM1_A14: J4.228(WE_n/A14) ; also on sheet 12
DDR4_DIMM1_A15: J4.86(CAS_n/A15) ; also on sheet 12
DDR4_DIMM1_A16: J4.82(RAS_n/A16) ; also on sheet 12
DDR4_DIMM1_A17: J4.234(A17/NC) ; also on sheet 12
DDR4_DIMM1_ACT_N: J4.62(ACT_n) ; also on sheet 12
DDR4_DIMM1_ALERT_N: J4.208(ALERT_n) R143.1 ; also on sheet 12
DDR4_DIMM1_BA0: J4.81(BA0) ; also on sheet 12
DDR4_DIMM1_BA1: J4.224(BA1) ; also on sheet 12
DDR4_DIMM1_BG0: J4.63(BG0) ; also on sheet 12
DDR4_DIMM1_BG1: J4.207(BG1) ; also on sheet 12
DDR4_DIMM1_C0: J4.93(S2_n/C0) ; also on sheet 12
DDR4_DIMM1_C1: J4.237(S3_n/C1) ; also on sheet 12
DDR4_DIMM1_CK_N0: J4.75(CK0_c) ; also on sheet 12
DDR4_DIMM1_CK_N1: J4.219(CK1_c) ; also on sheet 12
DDR4_DIMM1_CK_P0: J4.74(CK0_t) ; also on sheet 12
DDR4_DIMM1_CK_P1: J4.218(CK1_t) ; also on sheet 12
DDR4_DIMM1_CKE0: J4.60(CKE0) R141.2 ; also on sheet 12
DDR4_DIMM1_CKE1: J4.203(CKE1) R142.2 ; also on sheet 12
DDR4_DIMM1_CS_N0: J4.84(S0_n) ; also on sheet 12
DDR4_DIMM1_CS_N1: J4.89(S1_n) ; also on sheet 12
DDR4_DIMM1_DBI_N0: J4.7(DQS9_t/DM0_n/DBI0_n) ; also on sheet 12
DDR4_DIMM1_DBI_N1: J4.18(DQS10_t/DM1_n/DBI1_n) ; also on sheet 12
DDR4_DIMM1_DBI_N2: J4.29(DQS11_t/DM2_n/DBI2_n) ; also on sheet 13
DDR4_DIMM1_DBI_N3: J4.40(DQS12_t/DM3_n/DBI3_n) ; also on sheet 13
DDR4_DIMM1_DBI_N4: J4.99(DQS13_t/DM4_n/DBI4_n) ; also on sheet 12
DDR4_DIMM1_DBI_N5: J4.110(DQS14_t/DM5_n/DBI5_n) ; also on sheet 13
DDR4_DIMM1_DBI_N6: J4.121(DQS15_t/DM6_n/DBI6_n) ; also on sheet 12
DDR4_DIMM1_DBI_N7: J4.132(DQS16_t/DM7_n/DBI7_n) ; also on sheet 13
DDR4_DIMM1_DBI_N8: J4.51(DQS17_t/DM8_n/DBI8_n) ; also on sheet 13
DDR4_DIMM1_DQ0: J4.5(DQ0) ; also on sheet 12
DDR4_DIMM1_DQ1: J4.150(DQ1) ; also on sheet 12
DDR4_DIMM1_DQ2: J4.12(DQ2) ; also on sheet 12
DDR4_DIMM1_DQ3: J4.157(DQ3) ; also on sheet 12
DDR4_DIMM1_DQ4: J4.3(DQ4) ; also on sheet 12
DDR4_DIMM1_DQ5: J4.148(DQ5) ; also on sheet 12
DDR4_DIMM1_DQ6: J4.10(DQ6) ; also on sheet 12
DDR4_DIMM1_DQ7: J4.155(DQ7) ; also on sheet 12
DDR4_DIMM1_DQ8: J4.16(DQ8) ; also on sheet 12
DDR4_DIMM1_DQ9: J4.161(DQ9) ; also on sheet 12
DDR4_DIMM1_DQ10: J4.23(DQ10) ; also on sheet 12
DDR4_DIMM1_DQ11: J4.168(DQ11) ; also on sheet 12
DDR4_DIMM1_DQ12: J4.14(DQ12) ; also on sheet 12
DDR4_DIMM1_DQ13: J4.159(DQ13) ; also on sheet 12
DDR4_DIMM1_DQ14: J4.21(DQ14) ; also on sheet 12
DDR4_DIMM1_DQ15: J4.166(DQ15) ; also on sheet 12
DDR4_DIMM1_DQ16: J4.27(DQ16) ; also on sheet 13
DDR4_DIMM1_DQ17: J4.172(DQ17) ; also on sheet 13
DDR4_DIMM1_DQ18: J4.34(DQ18) ; also on sheet 13
DDR4_DIMM1_DQ19: J4.179(DQ19) ; also on sheet 13
DDR4_DIMM1_DQ20: J4.25(DQ20) ; also on sheet 13
DDR4_DIMM1_DQ21: J4.170(DQ21) ; also on sheet 13
DDR4_DIMM1_DQ22: J4.32(DQ22) ; also on sheet 13
DDR4_DIMM1_DQ23: J4.177(DQ23) ; also on sheet 13
DDR4_DIMM1_DQ24: J4.38(DQ24) ; also on sheet 13
DDR4_DIMM1_DQ25: J4.183(DQ25) ; also on sheet 13
DDR4_DIMM1_DQ26: J4.45(DQ26) ; also on sheet 13
DDR4_DIMM1_DQ27: J4.190(DQ27) ; also on sheet 13
DDR4_DIMM1_DQ28: J4.36(DQ28) ; also on sheet 13
DDR4_DIMM1_DQ29: J4.181(DQ29) ; also on sheet 13
DDR4_DIMM1_DQ30: J4.43(DQ30) ; also on sheet 13
DDR4_DIMM1_DQ31: J4.188(DQ31) ; also on sheet 13
DDR4_DIMM1_DQ32: J4.97(DQ32) ; also on sheet 12
DDR4_DIMM1_DQ33: J4.242(DQ33) ; also on sheet 12
DDR4_DIMM1_DQ34: J4.104(DQ34) ; also on sheet 12
DDR4_DIMM1_DQ35: J4.249(DQ35) ; also on sheet 12
DDR4_DIMM1_DQ36: J4.95(DQ36) ; also on sheet 12
DDR4_DIMM1_DQ37: J4.240(DQ37) ; also on sheet 12
DDR4_DIMM1_DQ38: J4.102(DQ38) ; also on sheet 12
DDR4_DIMM1_DQ39: J4.247(DQ39) ; also on sheet 12
DDR4_DIMM1_DQ40: J4.108(DQ40) ; also on sheet 13
DDR4_DIMM1_DQ41: J4.253(DQ41) ; also on sheet 13
DDR4_DIMM1_DQ42: J4.115(DQ42) ; also on sheet 13
DDR4_DIMM1_DQ43: J4.260(DQ43) ; also on sheet 13
DDR4_DIMM1_DQ44: J4.106(DQ44) ; also on sheet 13
DDR4_DIMM1_DQ45: J4.251(DQ45) ; also on sheet 13
DDR4_DIMM1_DQ46: J4.113(DQ46) ; also on sheet 13
DDR4_DIMM1_DQ47: J4.258(DQ47) ; also on sheet 13
DDR4_DIMM1_DQ48: J4.119(DQ48) ; also on sheet 12
DDR4_DIMM1_DQ49: J4.264(DQ49) ; also on sheet 12
DDR4_DIMM1_DQ50: J4.126(DQ50) ; also on sheet 12
DDR4_DIMM1_DQ51: J4.271(DQ51) ; also on sheet 12
DDR4_DIMM1_DQ52: J4.117(DQ52) ; also on sheet 12
DDR4_DIMM1_DQ53: J4.262(DQ53) ; also on sheet 12
DDR4_DIMM1_DQ54: J4.124(DQ54) ; also on sheet 12
DDR4_DIMM1_DQ55: J4.269(DQ55) ; also on sheet 12
DDR4_DIMM1_DQ56: J4.130(DQ56) ; also on sheet 13
DDR4_DIMM1_DQ57: J4.275(DQ57) ; also on sheet 13
DDR4_DIMM1_DQ58: J4.137(DQ58) ; also on sheet 13
DDR4_DIMM1_DQ59: J4.282(DQ59) ; also on sheet 13
DDR4_DIMM1_DQ60: J4.128(DQ60) ; also on sheet 13
DDR4_DIMM1_DQ61: J4.273(DQ61) ; also on sheet 13
DDR4_DIMM1_DQ62: J4.135(DQ62) ; also on sheet 13
DDR4_DIMM1_DQ63: J4.280(DQ63) ; also on sheet 13
DDR4_DIMM1_DQ64: J4.49(CB0/NC) ; also on sheet 13
DDR4_DIMM1_DQ65: J4.194(CB1/NC) ; also on sheet 13
DDR4_DIMM1_DQ66: J4.56(CB2/NC) ; also on sheet 13
DDR4_DIMM1_DQ67: J4.201(CB3/NC) ; also on sheet 13
DDR4_DIMM1_DQ68: J4.47(CB4/NC) ; also on sheet 13
DDR4_DIMM1_DQ69: J4.192(CB5/NC) ; also on sheet 13
DDR4_DIMM1_DQ70: J4.54(CB6/NC) ; also on sheet 13
DDR4_DIMM1_DQ71: J4.199(CB7/NC) ; also on sheet 13
DDR4_DIMM1_DQS_N0: J4.152(DQS0_c) ; also on sheet 12
DDR4_DIMM1_DQS_N1: J4.163(DQS1_c) ; also on sheet 12
DDR4_DIMM1_DQS_N2: J4.174(DQS2_c) ; also on sheet 13
DDR4_DIMM1_DQS_N3: J4.185(DQS3_c) ; also on sheet 13
DDR4_DIMM1_DQS_N4: J4.244(DQS4_c) ; also on sheet 12
DDR4_DIMM1_DQS_N5: J4.255(DQS5_c) ; also on sheet 13
DDR4_DIMM1_DQS_N6: J4.266(DQS6_c) ; also on sheet 12
DDR4_DIMM1_DQS_N7: J4.277(DQS7_c) ; also on sheet 13
DDR4_DIMM1_DQS_N8: J4.196(DQS8_c) ; also on sheet 13
DDR4_DIMM1_DQS_P0: J4.153(DQS0_t) ; also on sheet 12
DDR4_DIMM1_DQS_P1: J4.164(DQS1_t) ; also on sheet 12
DDR4_DIMM1_DQS_P2: J4.175(DQS2_t) ; also on sheet 13
DDR4_DIMM1_DQS_P3: J4.186(DQS3_t) ; also on sheet 13
DDR4_DIMM1_DQS_P4: J4.245(DQS4_t) ; also on sheet 12
DDR4_DIMM1_DQS_P5: J4.256(DQS5_t) ; also on sheet 13
DDR4_DIMM1_DQS_P6: J4.267(DQS6_t) ; also on sheet 12
DDR4_DIMM1_DQS_P7: J4.278(DQS7_t) ; also on sheet 13
DDR4_DIMM1_DQS_P8: J4.197(DQS8_t) ; also on sheet 13
DDR4_DIMM1_ODT0: J4.87(ODT0) ; also on sheet 12
DDR4_DIMM1_ODT1: J4.91(ODT1) ; also on sheet 12
DDR4_DIMM1_PAR: J4.222(PARITY) ; also on sheet 12
DDR4_DIMM1_RESET_N: J4.58(RESET_n) R139.1 R140.2 ; also on sheet 12
DDR4_DIMM1_SA0: J4.139(SA0) R136.2
DDR4_DIMM1_SA1: J4.140(SA1) R137.2
DDR4_DIMM1_SA2: J4.238(SA2/RFU) R138.2
DDR4_DIMM1_TDQS_N9: J4.8(DQS9_c) ; also on sheet 12
DDR4_DIMM1_TDQS_N10: J4.19(DQS10_c) ; also on sheet 12
DDR4_DIMM1_TDQS_N11: J4.30(DQS11_c) ; also on sheet 13
DDR4_DIMM1_TDQS_N12: J4.41(DQS12_c) ; also on sheet 13
DDR4_DIMM1_TDQS_N13: J4.100(DQS13_c) ; also on sheet 12
DDR4_DIMM1_TDQS_N14: J4.111(DQS14_c) ; also on sheet 13
DDR4_DIMM1_TDQS_N15: J4.122(DQS15_c) ; also on sheet 12
DDR4_DIMM1_TDQS_N16: J4.133(DQS16_c) ; also on sheet 13
DDR4_DIMM1_TDQS_N17: J4.52(DQS17_c) ; also on sheet 13
DDR4_DIMM2_A0: J5.79(A0) ; also on sheet 15
DDR4_DIMM2_A1: J5.72(A1) ; also on sheet 15
DDR4_DIMM2_A2: J5.216(A2) ; also on sheet 15
DDR4_DIMM2_A3: J5.71(A3) ; also on sheet 15
DDR4_DIMM2_A4: J5.214(A4) ; also on sheet 15
DDR4_DIMM2_A5: J5.213(A5) ; also on sheet 15
DDR4_DIMM2_A6: J5.69(A6) ; also on sheet 15
DDR4_DIMM2_A7: J5.211(A7) ; also on sheet 15
DDR4_DIMM2_A8: J5.68(A8) ; also on sheet 15
DDR4_DIMM2_A9: J5.66(A9) ; also on sheet 15
DDR4_DIMM2_A10: J5.225(A10/AP) ; also on sheet 15
DDR4_DIMM2_A11: J5.210(A11) ; also on sheet 15
DDR4_DIMM2_A12: J5.65(A12) ; also on sheet 15
DDR4_DIMM2_A13: J5.232(A13) ; also on sheet 15
DDR4_DIMM2_A14: J5.228(WE_n/A14) ; also on sheet 15
DDR4_DIMM2_A15: J5.86(CAS_n/A15) ; also on sheet 15
DDR4_DIMM2_A16: J5.82(RAS_n/A16) ; also on sheet 15
DDR4_DIMM2_A17: J5.234(A17/NC) ; also on sheet 15
DDR4_DIMM2_ACT_N: J5.62(ACT_n) ; also on sheet 15
DDR4_DIMM2_ALERT_N: J5.208(ALERT_n) R159.1 ; also on sheet 15
DDR4_DIMM2_BA0: J5.81(BA0) ; also on sheet 15
DDR4_DIMM2_BA1: J5.224(BA1) ; also on sheet 15
DDR4_DIMM2_BG0: J5.63(BG0) ; also on sheet 15
DDR4_DIMM2_BG1: J5.207(BG1) ; also on sheet 15
DDR4_DIMM2_C0: J5.93(S2_n/C0) ; also on sheet 15
DDR4_DIMM2_C1: J5.237(S3_n/C1) ; also on sheet 15
DDR4_DIMM2_CK_N0: J5.75(CK0_c) ; also on sheet 15
DDR4_DIMM2_CK_N1: J5.219(CK1_c) ; also on sheet 15
DDR4_DIMM2_CK_P0: J5.74(CK0_t) ; also on sheet 15
DDR4_DIMM2_CK_P1: J5.218(CK1_t) ; also on sheet 15
DDR4_DIMM2_CKE0: J5.60(CKE0) R157.2 ; also on sheet 15
DDR4_DIMM2_CKE1: J5.203(CKE1) R158.2 ; also on sheet 15
DDR4_DIMM2_CS_N0: J5.84(S0_n) ; also on sheet 15
DDR4_DIMM2_CS_N1: J5.89(S1_n) ; also on sheet 15
DDR4_DIMM2_DBI_N0: J5.7(DQS9_t/DM0_n/DBI0_n) ; also on sheet 15
DDR4_DIMM2_DBI_N1: J5.18(DQS10_t/DM1_n/DBI1_n) ; also on sheet 14
DDR4_DIMM2_DBI_N2: J5.29(DQS11_t/DM2_n/DBI2_n) ; also on sheet 14
DDR4_DIMM2_DBI_N3: J5.40(DQS12_t/DM3_n/DBI3_n) ; also on sheet 15
DDR4_DIMM2_DBI_N4: J5.99(DQS13_t/DM4_n/DBI4_n) ; also on sheet 14
DDR4_DIMM2_DBI_N5: J5.110(DQS14_t/DM5_n/DBI5_n) ; also on sheet 14
DDR4_DIMM2_DBI_N6: J5.121(DQS15_t/DM6_n/DBI6_n) ; also on sheet 15
DDR4_DIMM2_DBI_N7: J5.132(DQS16_t/DM7_n/DBI7_n) ; also on sheet 14
DDR4_DIMM2_DBI_N8: J5.51(DQS17_t/DM8_n/DBI8_n) ; also on sheet 15
DDR4_DIMM2_DQ0: J5.5(DQ0) ; also on sheet 15
DDR4_DIMM2_DQ1: J5.150(DQ1) ; also on sheet 15
DDR4_DIMM2_DQ2: J5.12(DQ2) ; also on sheet 15
DDR4_DIMM2_DQ3: J5.157(DQ3) ; also on sheet 15
DDR4_DIMM2_DQ4: J5.3(DQ4) ; also on sheet 15
DDR4_DIMM2_DQ5: J5.148(DQ5) ; also on sheet 15
DDR4_DIMM2_DQ6: J5.10(DQ6) ; also on sheet 15
DDR4_DIMM2_DQ7: J5.155(DQ7) ; also on sheet 15
DDR4_DIMM2_DQ8: J5.16(DQ8) ; also on sheet 14
DDR4_DIMM2_DQ9: J5.161(DQ9) ; also on sheet 14
DDR4_DIMM2_DQ10: J5.23(DQ10) ; also on sheet 14
DDR4_DIMM2_DQ11: J5.168(DQ11) ; also on sheet 14
DDR4_DIMM2_DQ12: J5.14(DQ12) ; also on sheet 14
DDR4_DIMM2_DQ13: J5.159(DQ13) ; also on sheet 14
DDR4_DIMM2_DQ14: J5.21(DQ14) ; also on sheet 14
DDR4_DIMM2_DQ15: J5.166(DQ15) ; also on sheet 14
DDR4_DIMM2_DQ16: J5.27(DQ16) ; also on sheet 14
DDR4_DIMM2_DQ17: J5.172(DQ17) ; also on sheet 14
DDR4_DIMM2_DQ18: J5.34(DQ18) ; also on sheet 14
DDR4_DIMM2_DQ19: J5.179(DQ19) ; also on sheet 14
DDR4_DIMM2_DQ20: J5.25(DQ20) ; also on sheet 14
DDR4_DIMM2_DQ21: J5.170(DQ21) ; also on sheet 14
DDR4_DIMM2_DQ22: J5.32(DQ22) ; also on sheet 14
DDR4_DIMM2_DQ23: J5.177(DQ23) ; also on sheet 14
DDR4_DIMM2_DQ24: J5.38(DQ24) ; also on sheet 15
DDR4_DIMM2_DQ25: J5.183(DQ25) ; also on sheet 15
DDR4_DIMM2_DQ26: J5.45(DQ26) ; also on sheet 15
DDR4_DIMM2_DQ27: J5.190(DQ27) ; also on sheet 15
DDR4_DIMM2_DQ28: J5.36(DQ28) ; also on sheet 15
DDR4_DIMM2_DQ29: J5.181(DQ29) ; also on sheet 15
DDR4_DIMM2_DQ30: J5.43(DQ30) ; also on sheet 15
DDR4_DIMM2_DQ31: J5.188(DQ31) ; also on sheet 15
DDR4_DIMM2_DQ32: J5.97(DQ32) ; also on sheet 14
DDR4_DIMM2_DQ33: J5.242(DQ33) ; also on sheet 14
DDR4_DIMM2_DQ34: J5.104(DQ34) ; also on sheet 14
DDR4_DIMM2_DQ35: J5.249(DQ35) ; also on sheet 14
DDR4_DIMM2_DQ36: J5.95(DQ36) ; also on sheet 14
DDR4_DIMM2_DQ37: J5.240(DQ37) ; also on sheet 14
DDR4_DIMM2_DQ38: J5.102(DQ38) ; also on sheet 14
DDR4_DIMM2_DQ39: J5.247(DQ39) ; also on sheet 14
DDR4_DIMM2_DQ40: J5.108(DQ40) ; also on sheet 14
DDR4_DIMM2_DQ41: J5.253(DQ41) ; also on sheet 14
DDR4_DIMM2_DQ42: J5.115(DQ42) ; also on sheet 14
DDR4_DIMM2_DQ43: J5.260(DQ43) ; also on sheet 14
DDR4_DIMM2_DQ44: J5.106(DQ44) ; also on sheet 14
DDR4_DIMM2_DQ45: J5.251(DQ45) ; also on sheet 14
DDR4_DIMM2_DQ46: J5.113(DQ46) ; also on sheet 14
DDR4_DIMM2_DQ47: J5.258(DQ47) ; also on sheet 14
DDR4_DIMM2_DQ48: J5.119(DQ48) ; also on sheet 15
DDR4_DIMM2_DQ49: J5.264(DQ49) ; also on sheet 15
DDR4_DIMM2_DQ50: J5.126(DQ50) ; also on sheet 15
DDR4_DIMM2_DQ51: J5.271(DQ51) ; also on sheet 15
DDR4_DIMM2_DQ52: J5.117(DQ52) ; also on sheet 15
DDR4_DIMM2_DQ53: J5.262(DQ53) ; also on sheet 15
DDR4_DIMM2_DQ54: J5.124(DQ54) ; also on sheet 15
DDR4_DIMM2_DQ55: J5.269(DQ55) ; also on sheet 15
DDR4_DIMM2_DQ56: J5.130(DQ56) ; also on sheet 14
DDR4_DIMM2_DQ57: J5.275(DQ57) ; also on sheet 14
DDR4_DIMM2_DQ58: J5.137(DQ58) ; also on sheet 14
DDR4_DIMM2_DQ59: J5.282(DQ59) ; also on sheet 14
DDR4_DIMM2_DQ60: J5.128(DQ60) ; also on sheet 14
DDR4_DIMM2_DQ61: J5.273(DQ61) ; also on sheet 14
DDR4_DIMM2_DQ62: J5.135(DQ62) ; also on sheet 14
DDR4_DIMM2_DQ63: J5.280(DQ63) ; also on sheet 14
DDR4_DIMM2_DQ64: J5.49(CB0/NC) ; also on sheet 15
DDR4_DIMM2_DQ65: J5.194(CB1/NC) ; also on sheet 15
DDR4_DIMM2_DQ66: J5.56(CB2/NC) ; also on sheet 15
DDR4_DIMM2_DQ67: J5.201(CB3/NC) ; also on sheet 15
DDR4_DIMM2_DQ68: J5.47(CB4/NC) ; also on sheet 15
DDR4_DIMM2_DQ69: J5.192(CB5/NC) ; also on sheet 15
DDR4_DIMM2_DQ70: J5.54(CB6/NC) ; also on sheet 15
DDR4_DIMM2_DQ71: J5.199(CB7/NC) ; also on sheet 15
DDR4_DIMM2_DQS_N0: J5.152(DQS0_c) ; also on sheet 15
DDR4_DIMM2_DQS_N1: J5.163(DQS1_c) ; also on sheet 14
DDR4_DIMM2_DQS_N2: J5.174(DQS2_c) ; also on sheet 14
DDR4_DIMM2_DQS_N3: J5.185(DQS3_c) ; also on sheet 15
DDR4_DIMM2_DQS_N4: J5.244(DQS4_c) ; also on sheet 14
DDR4_DIMM2_DQS_N5: J5.255(DQS5_c) ; also on sheet 14
DDR4_DIMM2_DQS_N6: J5.266(DQS6_c) ; also on sheet 15
DDR4_DIMM2_DQS_N7: J5.277(DQS7_c) ; also on sheet 14
DDR4_DIMM2_DQS_N8: J5.196(DQS8_c) ; also on sheet 15
DDR4_DIMM2_DQS_P0: J5.153(DQS0_t) ; also on sheet 15
DDR4_DIMM2_DQS_P1: J5.164(DQS1_t) ; also on sheet 14
DDR4_DIMM2_DQS_P2: J5.175(DQS2_t) ; also on sheet 14
DDR4_DIMM2_DQS_P3: J5.186(DQS3_t) ; also on sheet 15
DDR4_DIMM2_DQS_P4: J5.245(DQS4_t) ; also on sheet 14
DDR4_DIMM2_DQS_P5: J5.256(DQS5_t) ; also on sheet 14
DDR4_DIMM2_DQS_P6: J5.267(DQS6_t) ; also on sheet 15
DDR4_DIMM2_DQS_P7: J5.278(DQS7_t) ; also on sheet 14
DDR4_DIMM2_DQS_P8: J5.197(DQS8_t) ; also on sheet 15
DDR4_DIMM2_ODT0: J5.87(ODT0) ; also on sheet 15
DDR4_DIMM2_ODT1: J5.91(ODT1) ; also on sheet 15
DDR4_DIMM2_PAR: J5.222(PARITY) ; also on sheet 15
DDR4_DIMM2_RESET_N: J5.58(RESET_n) R155.1 R156.2 ; also on sheet 15
DDR4_DIMM2_SA0: J5.139(SA0) R152.1
DDR4_DIMM2_SA1: J5.140(SA1) R153.2
DDR4_DIMM2_SA2: J5.238(SA2/RFU) R154.2
DDR4_DIMM2_TDQS_N9: J5.8(DQS9_c) ; also on sheet 15
DDR4_DIMM2_TDQS_N10: J5.19(DQS10_c) ; also on sheet 14
DDR4_DIMM2_TDQS_N11: J5.30(DQS11_c) ; also on sheet 14
DDR4_DIMM2_TDQS_N12: J5.41(DQS12_c) ; also on sheet 15
DDR4_DIMM2_TDQS_N13: J5.100(DQS13_c) ; also on sheet 14
DDR4_DIMM2_TDQS_N14: J5.111(DQS14_c) ; also on sheet 14
DDR4_DIMM2_TDQS_N15: J5.122(DQS15_c) ; also on sheet 15
DDR4_DIMM2_TDQS_N16: J5.133(DQS16_c) ; also on sheet 14
DDR4_DIMM2_TDQS_N17: J5.52(DQS17_c) ; also on sheet 15
EN_G3: U74.7(EN) ; also on sheet 10 49 50
FPGA_VCCIO_1V2: C132.1 C133.1 C134.1 C135.1 C136.1 C137.1 C138.1 C139.1 C140.1 C141.1 C142.1 C143.1 C146.2 C147.2 C148.1 C149.1 C150.1 C151.1 C154.1 C155.1 C166.1 C167.1 C168.1 C169.1 C170.1 C171.1 C172.1 C173.1 C174.1 C175.1 C176.1 C177.1 C180.2 C181.2 C182.1 C183.1 C184.1 C185.1 C186.1 C188.1 C952.2 C953.2 C954.2 C955.2 J4.59(Vdd) J4.61(Vdd) J4.64(Vdd) J4.67(Vdd) J4.70(Vdd) J4.73(Vdd) J4.76(Vdd) J4.80(Vdd) J4.83(Vdd) J4.85(Vdd) J4.88(Vdd) J4.90(Vdd) J4.92(Vdd) J4.204(Vdd) J4.206(Vdd) J4.209(Vdd) J4.212(Vdd) J4.215(Vdd) J4.217(Vdd) J4.220(Vdd) J4.223(Vdd) J4.226(Vdd) J4.229(Vdd) J4.231(Vdd) J4.233(Vdd) J4.236(Vdd) J5.59(Vdd) J5.61(Vdd) J5.64(Vdd) J5.67(Vdd) J5.70(Vdd) J5.73(Vdd) J5.76(Vdd) J5.80(Vdd) J5.83(Vdd) J5.85(Vdd) J5.88(Vdd) J5.90(Vdd) J5.92(Vdd) J5.204(Vdd) J5.206(Vdd) J5.209(Vdd) J5.212(Vdd) J5.215(Vdd) J5.217(Vdd) J5.220(Vdd) J5.223(Vdd) J5.226(Vdd) J5.229(Vdd) J5.231(Vdd) J5.233(Vdd) J5.236(Vdd) R139.2 R143.2 R155.2 R159.2 R721.2 R722.2 U77.2(VLDOIN) U78.2(VLDOIN) ; also on sheet 10 16 23 25 26 27 31 34 35 36 39 50
FPGA_VCCIO_1V2_PG: R713.1 ; also on sheet 50
FPGA_VCCIO_SDM_HPS: C920.2 C921.2 C922.2 C923.2 R706.2 U74.1(VOUT1) U74.2(VOUT2) ; also on sheet 11 23 28 33 35 39 52
FPGA_VCCIO_SDM_HPS_PG: R704.2 R711.1 U74.4(POK)
FPGA_VCCR_CORE_PG: R712.1 ; also on sheet 49
PG_0V6_DDR4_VREF_COMP: R729.1 U78.9(PGOOD)
PG_0V6_DDR4_VREF_DIMM: R728.1 U77.9(PGOOD)
PG_2V5_DDR4_COMP: R727.1 U76.4(POK)
PG_2V5_DDR4_DIMM: R726.1 U75.4(POK)
PG_DDR4_LDO: R714.1 R725.2 R726.2 R727.2 R728.2 R729.2
PWRGD_G3: R709.1 R711.2 R712.2 R713.2 R714.2 ; also on sheet 10
N93250: J4.1(12V/NC) J4.145(12V/NC) R131.2 R132.2
N96922: J4.288(Vpp) R145.2
N1477892: C920.1 R706.1 R708.1 U74.3(VFB)
N1477908: C925.1 U74.6(SS)
N1551329: C928.1 R715.1 R719.1 U75.3(VFB)
N1551333: C929.1 R716.1 R720.1 U76.3(VFB)
N1551337: C936.1 U75.6(SS)
N1551419: C937.1 U76.6(SS)
N1551653: R717.2 U75.7(EN)
N1551693: R718.2 U76.7(EN)
N1553121: C962.1 R721.1 R723.1 U77.1(REFIN)
N1553157: C963.1 R722.1 R724.1 U78.1(REFIN)
N2975570: J5.1(12V/NC) J5.145(12V/NC) R147.2 R148.2
N2979144: J5.288(Vpp) R161.2

Not connected (* = marked no-connect by the designer): J4 144(RFU1)* 205(RFU2)* 227(RFU3)*; J5 144(RFU1)* 205(RFU2)* 227(RFU3)*; U74 8(NC)*; U75 8(NC)*; U76 8(NC)*

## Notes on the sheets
sheet 53
- Vout = 0.5V x (Rup/Rdn + 1)
- VDOmax = 185mV
- (Includes VBAT and VCCFUSEWR_SDM)
- 1.8V +/-2.7% @ 10mA
- VINabsmax = -0.3V to 6.5V
- Rup
- Rdn
- ENth = 0.3V /0.8V / 1V
  ABSmax = 6.5V
sheet 54
- VDOmax = 185mV
- VDOmax = 185mV
- VINabsmax = -0.3V to 6.5V
- Vout = 0.5V x (Rup/Rdn + 1)
- VINabsmax = -0.3V to 6.5V
- Vout = 0.5V x (Rup/Rdn + 1)
- Rup
- Rup
- Rdn
- Rdn
- ENth = 0.616V /0.8V / 0.95V
- ENth = 0.616V /0.8V / 0.95V
- Vih=1.7, Vil = 0.3
- Absmax = 6.5V
- 0.6V
- 0.6V
- Alternate:  ON-Semi NCP51200
- Alternate:  ON-Semi NCP51200
- Pullup by R709 on pg57
sheet 55
- DDR4/DDR-T DIMM 1
- DDR4 DIMM1 IF
- I2C Addr: 0xA0
- Pull-ups on PG38
- Put caps on VDD pins which are close to DIMM A/C pins
sheet 56
- DDR4/DDR-T DIMM 2
- DDR4 DIMM2 IF
- I2C Addr: 0xA1
- Pull-ups on PG38
- Put caps on VDD pins which are close to DIMM A/C pins
sheet 57
- DDR4/DDR-T DIMM Pin Map
- DDR-T DIMM Pin Map is Identical
  to standard DDR4 DIMM Pin Map
  except the DDR-T protocol
  repurposes five of these pins:
- CS1# (pin 89) : Grant, GNT# <0>  Input
- CKE1 (pin 203) : Request, REQ# <0> Output
- ODT1 (pin 91) : Error, ERR#      Output
- CLK1 (pin 218):Early Read ID, ERID<0>  Output
- CLK1# (pin 219):Early Read ID, ERID<1>  Output
